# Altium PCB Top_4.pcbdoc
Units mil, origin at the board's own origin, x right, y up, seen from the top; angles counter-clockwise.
Board outline 3537.2 x 1973 mil, 4 copper layers (Top Layer, Inner1, Inner2, Bottom Layer), stack 97.3 mil thick; 147 components, 104 nets, 518 pads, 152 vias.
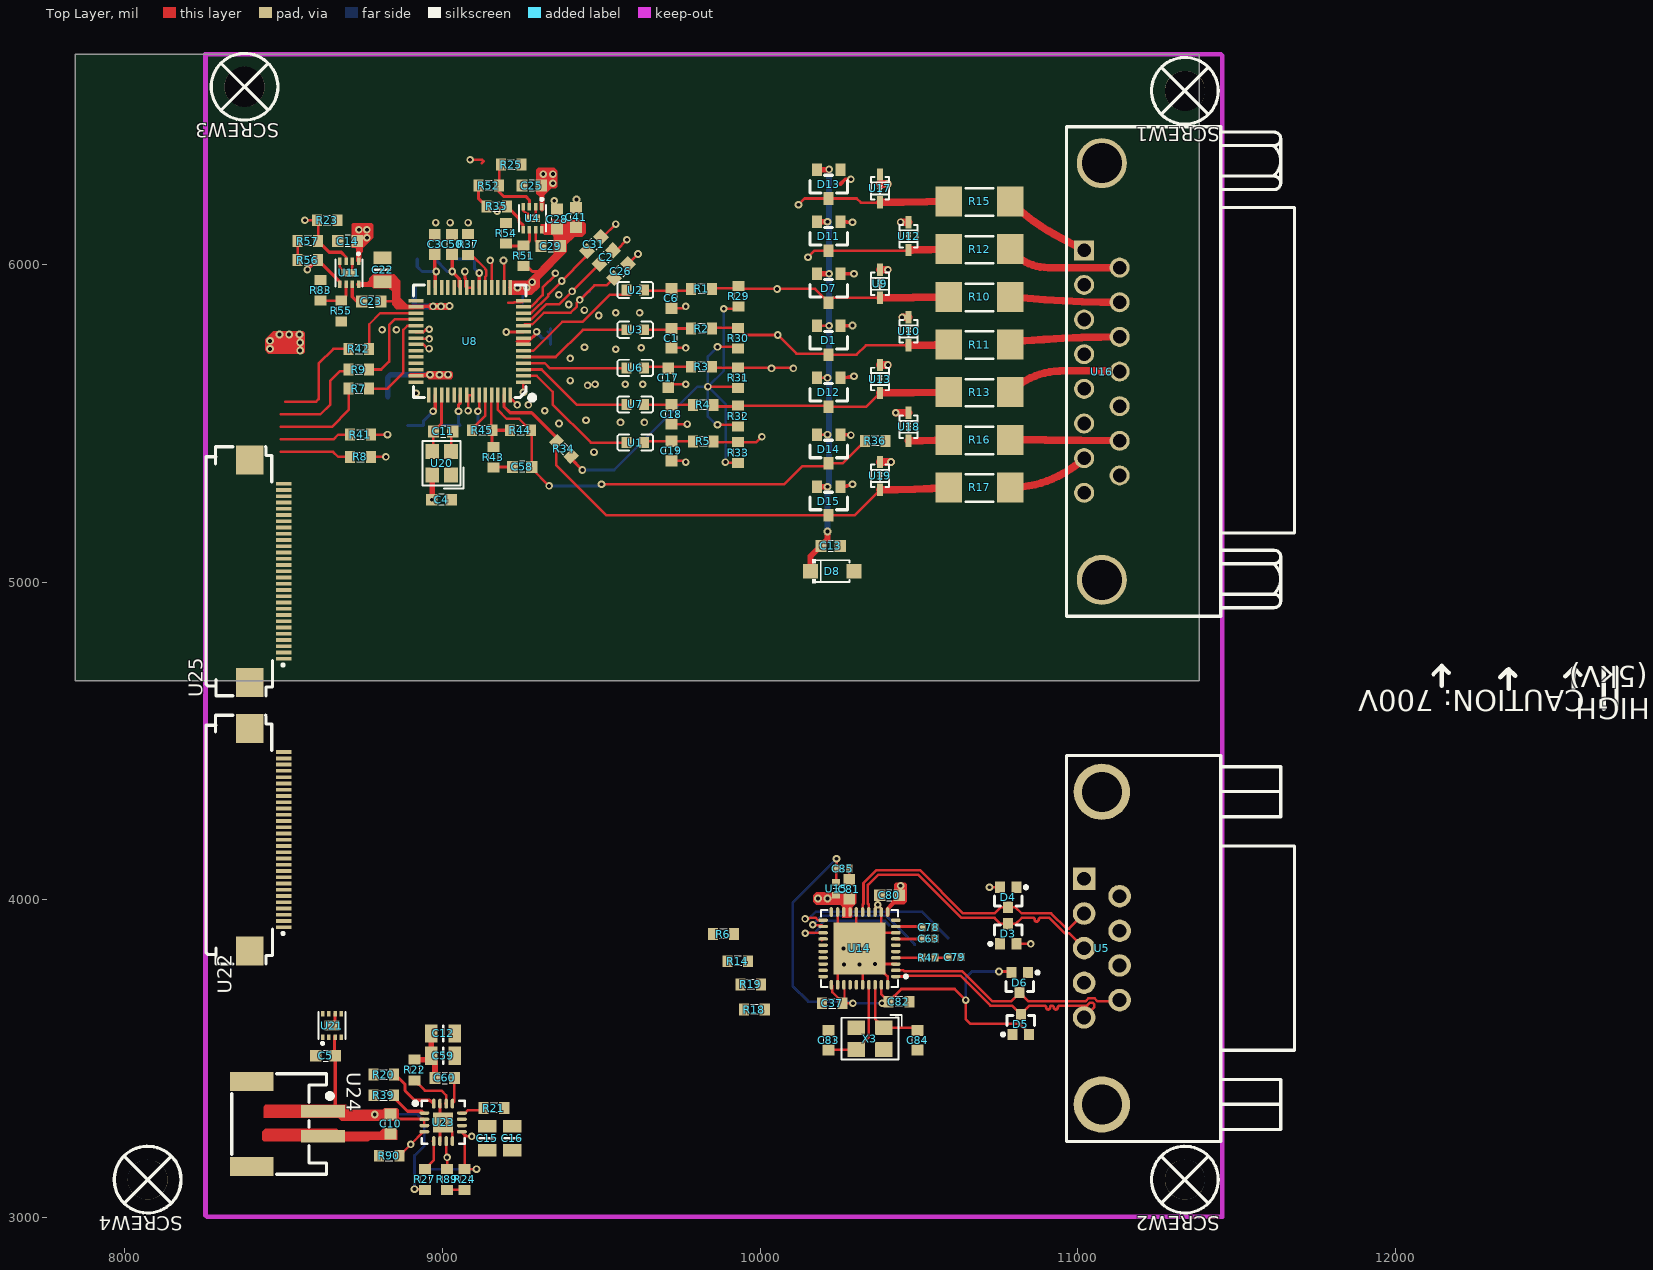
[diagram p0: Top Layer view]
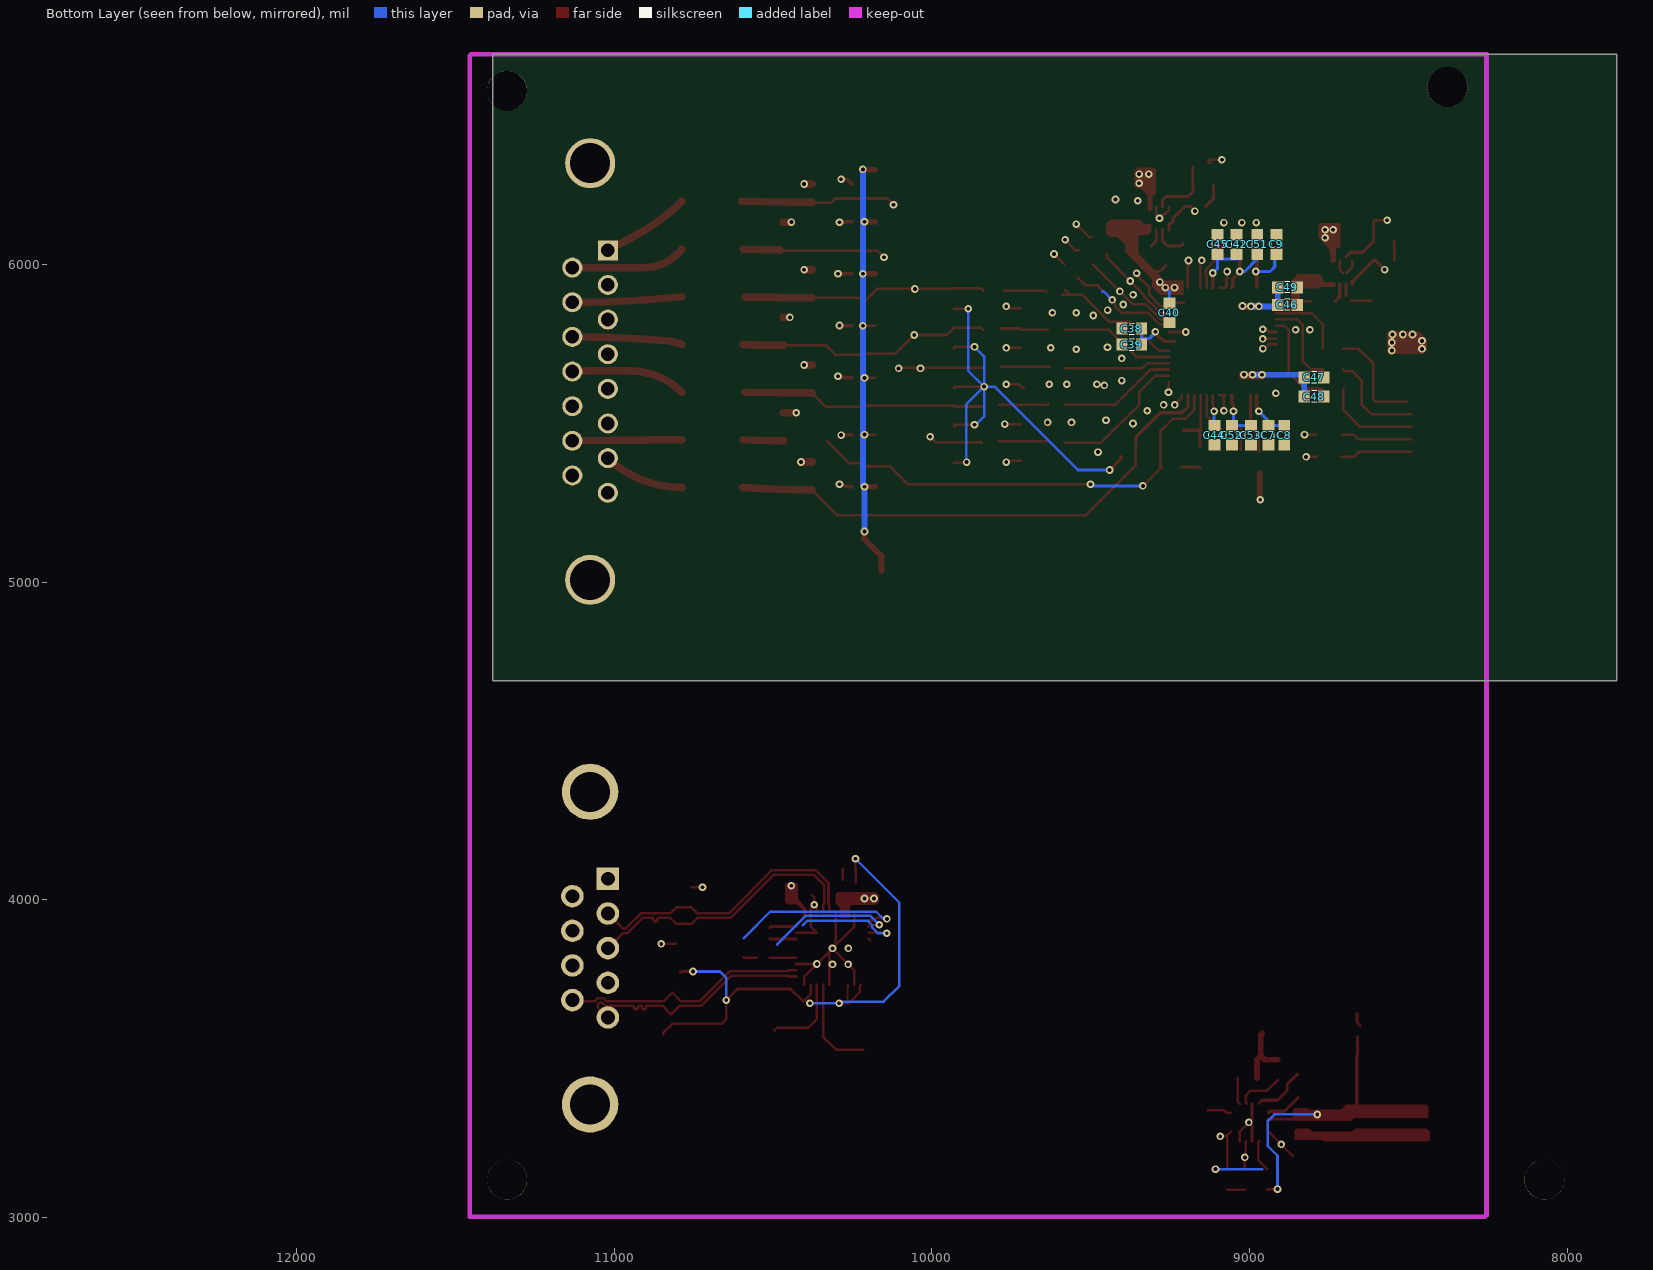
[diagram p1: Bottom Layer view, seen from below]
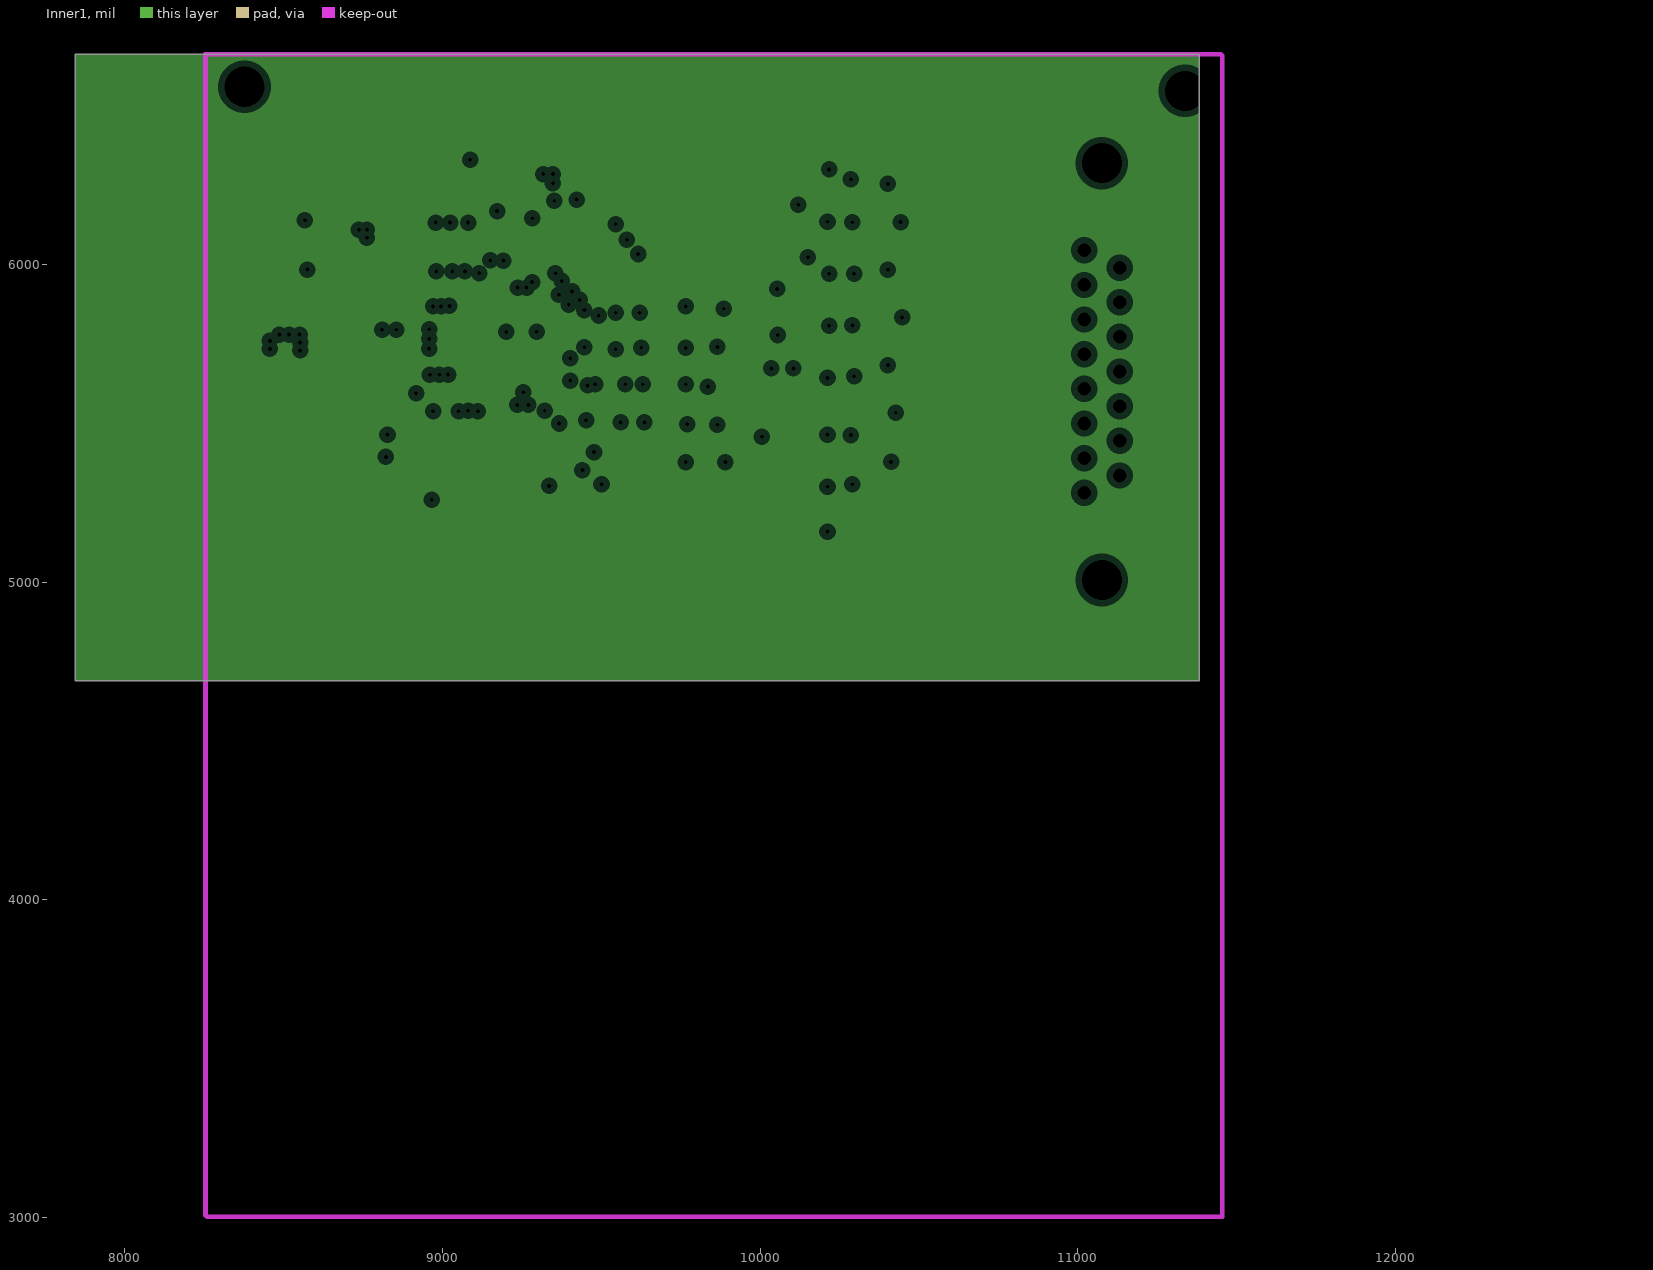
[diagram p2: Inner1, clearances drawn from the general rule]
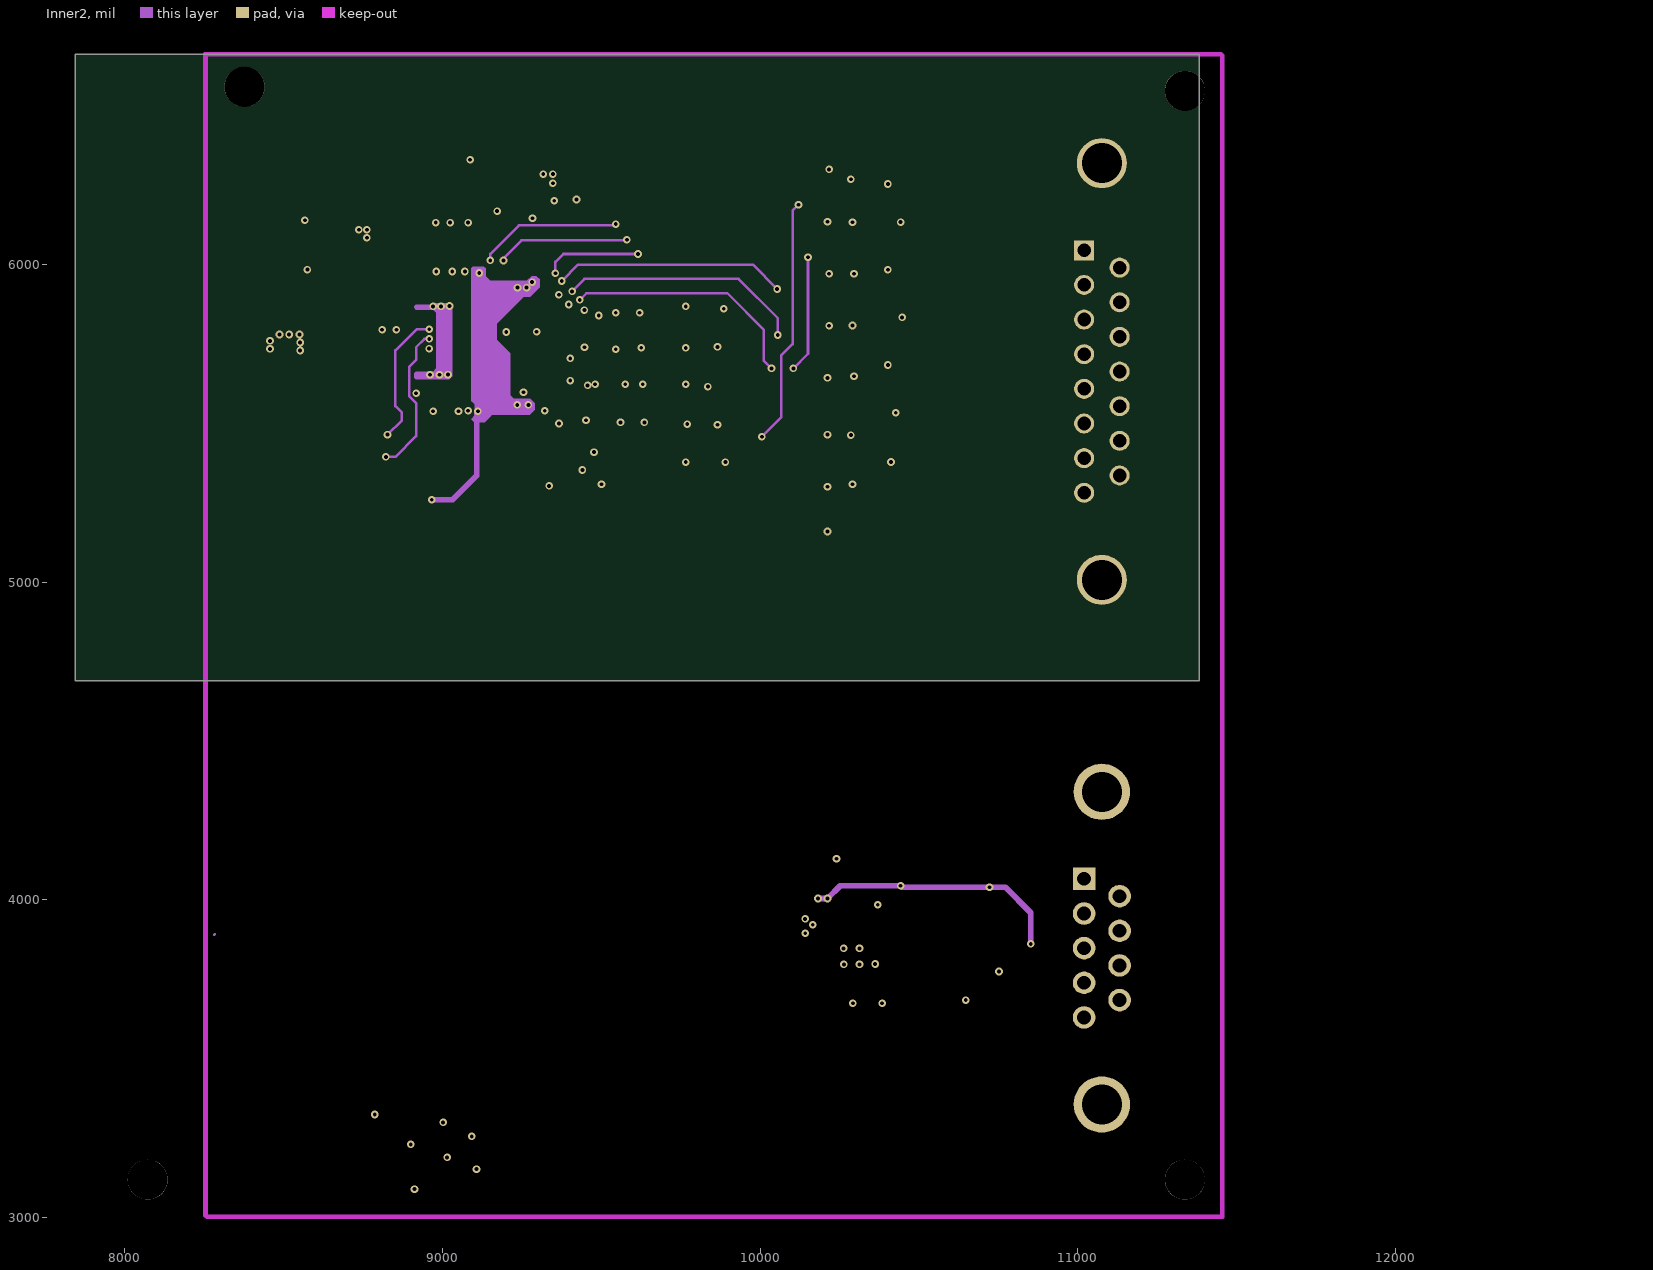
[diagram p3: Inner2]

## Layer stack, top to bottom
Top Solder Mask Layer: solder mask 0.4, Dk 3.3
Top Layer: signal copper 1.4
Inner1: plane copper (thickness not stored)
Inner2: signal copper (thickness not stored)
Dielectric2: surface 18.9, FR4, Dk 4.5
Dielectric3: surface 18.9, PP, Dk 4.5
Dielectric4: surface 18.9, PP, Dk 4.5
Dielectric5: surface 18.9, FR4, Dk 4.5
Dielectric6: surface 18.9, PP, Dk 4.5
Bottom Layer: signal copper 1.4
Bottom Solder Mask Layer: solder mask 0.4, Dk 3.3

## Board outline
7845,6662.7 11382.2,6662.7 11382.2,4689.7 7845,4689.7

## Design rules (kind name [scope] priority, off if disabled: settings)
BoardOutlineClearance copperThickness1oz [All] p0: genericclearance=10 ignorepadtopadclearanceinfootprint=FALSE except(0: Arc-SplitContinuation Track-SplitContinuation SMDPad-SplitContinuation THPad-SplitContinuation Via-SplitContinuation Fill-SplitContinuation Poly-SplitContinuation Region-SplitContinuation Text-SplitContinuation)
BoardOutlineClearance copperThickness2oz [All] p0: genericclearance=10 ignorepadtopadclearanceinfootprint=FALSE except(0: Arc-SplitContinuation Track-SplitContinuation SMDPad-SplitContinuation THPad-SplitContinuation Via-SplitContinuation Fill-SplitContinuation Poly-SplitContinuation Region-SplitContinuation Text-SplitContinuation)
BoardOutlineClearance copperThicknessInner0.5oz [All] p0: genericclearance=10 ignorepadtopadclearanceinfootprint=FALSE except(0: Arc-SplitContinuation Track-SplitContinuation SMDPad-SplitContinuation THPad-SplitContinuation Via-SplitContinuation Fill-SplitContinuation Poly-SplitContinuation Region-SplitContinuation Text-SplitContinuation)
BoardOutlineClearance otherClearance [All] p0: genericclearance=10 ignorepadtopadclearanceinfootprint=FALSE except(0: Arc-SplitContinuation Track-SplitContinuation SMDPad-SplitContinuation THPad-SplitContinuation Via-SplitContinuation Fill-SplitContinuation Poly-SplitContinuation Region-SplitContinuation Text-SplitContinuation)
Clearance copperThickness1oz [All] p1: gap=7 ignorepadtopadclearanceinfootprint=FALSE
Clearance copperThickness2oz [(InNet('AVDD') OR InNet('$28N49'))] p1: gap=7 ignorepadtopadclearanceinfootprint=FALSE
Clearance copperThicknessInner0.5oz [All] p1: gap=7 ignorepadtopadclearanceinfootprint=FALSE
Clearance otherClearance [All] p1: gap=7 ignorepadtopadclearanceinfootprint=FALSE
DiffPairsRouting differentialPair [All] p1: maxuncoupledlength=10 minlimit=5.9843 maxlimit=Infinity mostfreqgap=5.9843 toplayer_minwidth=5 toplayer_prefwidth=10 toplayer_maxwidth=100 bottomlayer_minwidth=5 bottomlayer_prefwidth=10 bottomlayer_maxwidth=100 midlayer1_minwidth=5 midlayer1_prefwidth=10 midlayer1_maxwidth=100
PasteMaskExpansion pasteMaskExpansion [All] p1: expansion=0
PlaneConnect innerPlane [All] p1: planeconnectstyle=Relief reliefexpansion=20 reliefentries=4 reliefconductorwidth=10 reliefairgap=10
PolygonConnect copperRegion [All] p1: connectstyle=Relief reliefentries=4 reliefconductorwidth=10 polygonreliefangle="90 Angle" airgapwidth=10
PolygonConnect copperRegion1 [All] p1: connectstyle=Direct reliefentries=4 reliefconductorwidth=10 polygonreliefangle="90 Angle" airgapwidth=10
RoutingVias viaSize [All] p1: viastyle="Through Hole" holewidth=12.0078 minholewidth=7.874 maxholewidth=248.0314 width=12.0078 minwidth=7.874 maxwidth=248.0314
SolderMaskExpansion solderMaskExpansion [IsVia] p1: useseparateexpansions=TRUE expansion=-1000 expansionbottom=-1000
SolderMaskExpansion solderMaskExpansion [All] p2: useseparateexpansions=TRUE expansion=2.0079 expansionbottom=2.0079
Width copperThickness1oz [All] p1: maxlimit=100 minlimit=4 preferedwidth=10
Width copperThickness2oz [All] p1: maxlimit=100 minlimit=8 preferedwidth=10
Width copperThickness0.5oz [All] p1: maxlimit=100 minlimit=4 preferedwidth=10

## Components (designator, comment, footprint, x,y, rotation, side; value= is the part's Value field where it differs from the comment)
C1 "100nF" C0603#1 9720.8,5768.3 r90 top
C2 "100nF" C0603#1 9515.8,6023.3 r45 top
C3 "100nF" C0603#1 8975.8,6063.3 r270 top
C4 "20pF" C0603#1 8997.2,5259.7 r180 top
C5 "100nF" C0603#1 8632.2,3509.7 r0 top
C6 "100nF" C0603#1 9720.8,5893.3 r90 top
C7 "100nF" C0603#1 8940.8,5463.3 r90 bottom
C8 "100nF" C0603#1 8890.8,5463.3 r90 bottom
C9 "100nF" C0603#1 8915.8,6063.3 r270 bottom
C10 "10uF" C0603#2 8837.2,3294.7 r90 top
C11 "20pF" C0603#1 9002.2,5474.7 r0 top
C12 "10uF" C0603#3 9002.2,3579.7 r0 top
C13 "10uF" C0603#1 10222.2,5114.7 r0 top
C14 "100nF" C0603#2 8701.5,6073.9 r180 top
C15 "10uF" C0603#3 9141,3249.5 r90 top
C16 "10uF" C0603#3 9219.8,3250.2 r90 top
C17 "100nF" C0603#1 9710.8,5643.3 r90 top
C18 "100nF" C0603#1 9720.8,5528.3 r90 top
C19 "100nF" C0603#1 9720.8,5413.3 r90 top
C22 "100nF" C0603#4 8811.5,5983.9 r270 top
C23 "100nF" C0603#5 8776.5,5883.9 r0 top
C25 "100nF" C0603#1 9280.8,6248.3 r180 top
C26 "100nF" C0603#6 9562.2,5979.7 r45 top
C28 "100nF" C0603#1 9360.8,6143.3 r270 top
C29 "100nF" C0603#1 9340.8,6058.3 r0 top
C31 "100nF" C0603#6 9477.2,6064.7 r45 top
C37 "100nF" C0603#7 10227.2,3674.7 r0 top
C38 "100nF" C0603#1 9370.8,5798.3 r180 bottom
C39 "100nF" C0603#1 9370.8,5748.3 r180 bottom
C40 "100nF" C0603#1 9252.3,5848 r90 bottom
C41 "100nF" C0603#1 9420.8,6148.3 r270 top
C42 "100nF" C0603#1 9040.8,6063.3 r270 bottom
C44 "100nF" C0603#1 9110.8,5463.3 r90 bottom
C45 "100nF" C0603#1 9100.8,6063.3 r270 bottom
C46 "100nF" C0603#1 8880.8,5873.3 r0 bottom
C47 "100nF" C0603#1 8797.2,5644.7 r0 bottom
C48 "100nF" C0603#1 8797.2,5584.7 r0 bottom
C49 "100nF" C0603#1 8880.8,5928.3 r0 bottom
C50 "100nF" C0603#1 9030.8,6063.3 r270 top
C51 "100nF" C0603#1 8975.8,6063.3 r270 bottom
C52 "100nF" C0603#1 9055.8,5463.3 r90 bottom
C53 "100nF" C0603#1 8995.8,5463.3 r90 bottom
C58 "100nF" C0603#1 9250.8,5363.3 r180 top
C59 "10uF" C0603#3 9002.2,3509.7 r0 top
C60 "100nF" C0603#1 9007.2,3439.7 r0 top
C63 "100nF" C0603#8 10530.8,3878.3 r180 top
C78 "100nF" C0603#8 10530.8,3913.3 r180 top
C79 "100nF" C0603#8 10612.2,3819.7 r180 top
C80 "100nF" C0603#1 10407.2,4014.7 r0 top
C81 "100nF" C0603#1 10280.8,4033.3 r270 top
C82 "100nF" C0603#7 10437.2,3679.7 r180 top
C83 "100nF" C0603#1 10215.8,3558.3 r270 top
C84 "100nF" C0603#1 10495.8,3558.3 r270 top
C85 "100nF" C0603#8 10260.8,4098.3 r180 top
D1 "BAV199LT1G" SOT-23_L2.9-W1.3-P1.90-LS2.4-BR#1 10215.8,5762 r90 top
D3 "BAV99W-7-F" SOT-323_L2.0-W1.3-P1.30-LS2.1-BR 10780.8,3893.3 r270 top
D4 "BAV99W-7-F" SOT-323_L2.0-W1.3-P1.30-LS2.1-BR 10780.8,4008.3 r90 top
D5 "BAV99W-7-F" SOT-323_L2.0-W1.3-P1.30-LS2.1-BR 10820.8,3608.3 r270 top
D6 "BAV99W-7-F" SOT-323_L2.0-W1.3-P1.30-LS2.1-BR 10817.3,3739.8 r90 top
D7 "BAV199LT1G" SOT-23_L2.9-W1.3-P1.90-LS2.4-BR#2 10215.8,5925.7 r90 top
D8 "SMF3.3A" SOD-123FL_L2.7-W1.8-LS3.7-RD 10227.2,5034.7 r0 top
D11 "BAV199LT1G" SOT-23_L2.9-W1.3-P1.90-LS2.4-BR#3 10215.8,6089.5 r90 top
D12 "BAV199LT1G" SOT-23_L2.9-W1.3-P1.90-LS2.4-BR#1 10215.8,5598.2 r90 top
D13 "BAV199LT1G" SOT-23_L2.9-W1.3-P1.90-LS2.4-BR#3 10215.8,6253.3 r90 top
D14 "BAV199LT1G" SOT-23_L2.9-W1.3-P1.90-LS2.4-BR#3 10215.8,5419.4 r90 top
D15 "BAV199LT1G" SOT-23_L2.9-W1.3-P1.90-LS2.4-BR#3 10215.8,5255.6 r90 top
R1 "10K" R0603#1 9815.8,5923.3 r180 top
R2 "10K" R0603#1 9815.8,5798.3 r180 top
R3 "10K" R0603#1 9815.8,5678.3 r180 top
R4 "10K" R0603#1 9820.8,5558.3 r180 top
R5 "10K" R0603#1 9820.8,5443.3 r180 top
R6 "10K" R0603#1 9884.7,3892.2 r180 top
R7 "10K" R0603#1 8737.2,5609.7 r0 top
R8 "10K" R0603#1 8742.2,5394.7 r0 top
R9 "10K" R0603#1 8737.2,5669.7 r0 top
R10 "5.1kΩ" R0207 10690.8,5898.3 r180 top
R11 "5.1kΩ" R0207 10690.8,5748.3 r180 top
R12 "5.1kΩ" R0207 10690.8,6048.3 r180 top
R13 "5.1kΩ" R0207 10690.8,5598.3 r180 top
R14 "10K" R0603#1 9929.7,3807.2 r180 top
R15 "5.1kΩ" R0207 10690.8,6199.1 r180 top
R16 "5.1kΩ" R0207 10690.8,5448.3 r180 top
R17 "5.1kΩ" R0207 10690.8,5298.3 r180 top
R18 "10K" R0603#1 9982.2,3654.7 r180 top
R19 "10K" R0603#2 9970.5,3734.4 r180 top
R20 "10K" R0603#2 8814.8,3450.2 r0 top
R21 "10K" R0603#1 9162.2,3344.7 r180 top
R22 "10K" R0603#3 8912.2,3464.7 r270 top
R23 "10K" R0603#1 8637.2,6139.7 r0 top
R24 "10K" R0603#1 9069.8,3120.2 r270 top
R25 "10K" R0603#1 9217.2,6314.7 r0 top
R27 "10K" R0603#1 8944.8,3120.2 r90 top
R29 "10K" R0603#3 9932.2,5899.7 r270 top
R30 "10K" R0603#1 9930.8,5768.3 r90 top
R31 "10K" R0603#1 9930.8,5643.3 r270 top
R32 "10K" R0603#1 9930.8,5523.3 r90 top
R33 "10K" R0603#1 9930.8,5408.3 r270 top
R34 "10K" R0603#4 9382.2,5419.7 r315 top
R35 "10K" R0603#1 9170.8,6183.3 r0 top
R36 "10K" R0603#1 10362.2,5444.7 r180 top
R37 "10K" R0603#1 9080.8,6063.3 r90 top
R39 "MF52" RES-TH_L2.5-W2.5-P1.70-D0.3 8814.8,3385.2 r0 top
R41 "10K" R0603#1 8742.2,5464.7 r0 top
R42 "10K" R0603#1 8737.2,5734.7 r0 top
R43 "10K" R0603#1 9160.8,5393.3 r90 top
R44 "10K" R0603#1 9245.8,5478.3 r180 top
R45 "10K" R0603#1 9125.8,5478.3 r180 top
R47 "10K" R0603#5 10530.8,3818.3 r180 top
R51 "10K" R0603#1 9255.8,6028.3 r270 top
R52 "10K" R0603#1 9145.8,6248.3 r180 top
R54 "10K" R0603#1 9200.8,6098.3 r270 top
R55 "10K" R0603#3 8681.5,5853.9 r270 top
R56 "10K" R0603#3 8576.5,6013.9 r0 top
R57 "10K" R0603#2 8576.5,6073.9 r180 top
R83 "10K" R0603#3 8616.5,5918.9 r270 top
R89 "10K" R0603#1 9014.8,3120.2 r270 top
R90 "10K" R0603#1 8832.2,3194.7 r0 top
SCREW1 "" M3螺丝 11337.2,6546.9 r180 top
SCREW2 "" M3螺丝 11337.2,3119.7 r180 top
SCREW3 "" M3螺丝 8377.2,6559.7 r180 top
SCREW4 "" M3螺丝 8072.2,3119.7 r180 top
U1 "YI160808U601-2R0T" L0603#1 9607.2,5439.7 r180 top
U2 "YI160808U601-2R0T" L0603#1 9607.2,5919.7 r180 top
U3 "YI160808U601-2R0T" L0603#1 9607.2,5794.7 r180 top
U4 "TPL9053AD-DF4R" TDFN-8_L2.0-W2.0-P0.50-BL-EP1.2-1#1 9283.5,6145.6 r270 top
U5 "D-SUB-DR-9PCM-CB" DB9-TH_D-SUB-DR-9PCM-CB 11075.8,3848.3 r90 top
U6 "YI160808U601-2R0T" L0603#1 9607.2,5674.7 r180 top
U7 "YI160808U601-2R0T" L0603#1 9607.2,5559.7 r180 top
U8 "" ? 9085.8,5758.3 r90 top
U9 "SP4024-01FTG-C" SOD-323_L1.8-W1.3-LS2.5-BI 10377.2,5939.7 r270 top
U10 "SP4024-01FTG-C" SOD-323_L1.8-W1.3-LS2.5-BI 10467.2,5789.7 r270 top
U11 "TPL9053AD-DF4R" TDFN-8_L2.0-W2.0-P0.50-BL-EP1.2-1#2 8706.5,5973.9 r270 top
U12 "SP4024-01FTG-C" SOD-323_L1.8-W1.3-LS2.5-BI 10467.2,6089.7 r270 top
U13 "SP4024-01FTG-C" SOD-323_L1.8-W1.3-LS2.5-BI 10377.2,5639.7 r270 top
U14 "AFE4400RHAR" VQFN-40_L6.0-W6.0-P0.50-TL-EP4.2 10312.9,3847.5 r180 top
U15 "BLM18PG121SN1D" L0603#2 10239.7,4034.9 r270 top
U16 "D-SUB-DR-15PCM-CB" DSUB-TH_XUNPU_D-SUB-DR-15PCM-CB 11075.8,5663.3 r90 top
U17 "SP4024-01FTG-C" SOD-323_L1.8-W1.3-LS2.5-BI 10377.2,6239.7 r270 top
U18 "SP4024-01FTG-C" SOD-323_L1.8-W1.3-LS2.5-BI 10467.2,5489.7 r270 top
U19 "SP4024-01FTG-C" SOD-323_L1.8-W1.3-LS2.5-BI 10377.2,5334.7 r270 top
U20 "8.192MHz" OSC-SMD_4P-L2.5-W2.0-BL 8997.2,5374.7 r90 top
U21 "MAX17048G+T10" TDFN-8_L2.0-W2.0-P0.50-BL-EP1.2 8652.2,3604.7 r0 top
U22 "AFD01-S29FCA-00" FPC-SMD_29P-P0.50_JS_AFD01-S29FCA-00 8447.2,4189.7 r90 top
U23 "BQ24072RGTR" QFN-16_L3.0-W3.0-P0.50-TL-EP 9002.2,3299.7 r0 top
U24 "ZX-PH2.0-WT2P" CONN-SMD_ZX-PH2.0-WT2P 8512.2,3294.7 r270 top
U25 "AFD01-S29FCA-00" FPC-SMD_29P-P0.50_JS_AFD01-S29FCA-00 8447.2,5034.7 r90 top
X3 "8MHz" CRYSTAL-SMD_4P-L3.2-W2.5-BL-1 10345.8,3563.3 r180 top

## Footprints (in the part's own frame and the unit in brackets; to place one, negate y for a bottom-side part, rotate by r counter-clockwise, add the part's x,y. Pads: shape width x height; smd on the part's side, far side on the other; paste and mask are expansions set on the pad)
C0603#1 [mil]
  rect 35.4x37.4 smd: 1(-30.5,0) 2(30.5,0)
  silkscreen extent -8,-18 8,18
C0603#2 [mil]
  rect 35.4x37.4 smd: 1(-30.5,0) 2(30.6,0)
  silkscreen extent -8,-18 8,18
C0603#3 [mil]
  rect 39.4x57.1 smd: 1(-37.4,0) 2(37.4,0)
  silkscreen extent 0,-25 0,25
C0603#4 [mil]
  rect 39.4x57.1 smd: 1(-37.4,0) 2(37.3,0)
  silkscreen extent 0,-25 0,25
C0603#5 [mil]
  rect 35.4x37.4 smd: 1(-30.6,0) 2(30.5,0)
  silkscreen extent -8,-18 8,18
C0603#6 [mil]
  rect 35.4x37.4 smd: 1(-30.48,0.07) 2(30.55,0)
  silkscreen extent -8,-18 8,18
C0603#7 [mil]
  rect 31.5x37.4 smd: 1(-32.5,0) 2(32.5,0)
  silkscreen extent -12,-15 12,15
C0603#8 [mil]
  rect 21.3x25.2 smd: 1(-20.1,0) 2(20.1,0)
  silkscreen extent 0,-10 0,10
CONN-SMD_ZX-PH2.0-WT2P [mil]
  rect 39.4x137.8 smd: 1(-39.4,112.2) 2(39.3,112.2)
  rect 59.1x137.8 smd: 3(-133.9,-112.2) 4(133.8,-112.2)
  silkscreen extent -158,-175 158,141
CRYSTAL-SMD_4P-L3.2-W2.5-BL-1 [mil]
  rect 55.1x47.2 smd: 1(-43.3,-34.4) 2(43.3,-34.4) 3(43.3,34.5) 4(-43.3,34.5)
  silkscreen extent -100,-75 90,65
DB9-TH_D-SUB-DR-9PCM-CB [mil]
  rect 70.9x70.9 hole 43.3: 1(218.1,55.9)
  round 70.9 hole 43.3: 2(109,55.9) 3(0,55.9) 4(-109.1,55.9) 5(-218.1,55.9) 6(163.6,-55.9) 7(54.5,-55.9) 8(-54.5,-55.9) 9(-163.6,-55.9)
  round 177.2 hole 126: 10(-492.1,0) 11(492.1,0)
  silkscreen extent -609,-606 606,111
DSUB-TH_XUNPU_D-SUB-DR-15PCM-CB [mil]
  rect 63x63 hole 42.9 paste+0 mask+2: 1(381.7,55.9)
  round 63 hole 42.9 paste+0 mask+2: 2(272.6,55.9) 3(163.6,55.9) 4(54.5,55.9) 5(-54.5,55.9) 6(-163.6,55.9) 7(-272.6,55.9) 8(-381.7,55.9) 9(327.2,-55.9) 10(218.1,-55.9) 11(109.1,-55.9) 12(0,-55.9) 13(-109.1,-55.9) 14(-218.1,-55.9) 15(-327.2,-55.9)
  round 157.5 hole 126 paste+0 mask+2: 16(-655.9,0) 17(655.9,0)
  silkscreen extent -770,-606 770,111
FPC-SMD_29P-P0.50_JS_AFD01-S29FCA-00 [mil]
  rect 11.8x49.2 smd paste+0 mask+2: 1(-275.5,-53.6) 2(-255.9,-53.6) 3(-236.2,-53.6) 4(-216.5,-53.6) 5(-196.8,-53.6) 6(-177.1,-53.6) 7(-157.4,-53.6) 8(-137.8,-53.6) 9(-118.1,-53.6) 10(-98.4,-53.6) 11(-78.7,-53.6) 12(-59,-53.6) 13(-39.3,-53.6) 14(-19.7,-53.6) 15(0,-53.6) 16(19.7,-53.6) 17(39.4,-53.6) 18(59.1,-53.6) 19(78.8,-53.6) 20(98.5,-53.6) 21(118.1,-53.6) 22(137.8,-53.6) 23(157.5,-53.6) 24(177.2,-53.6) 25(196.9,-53.6) 26(216.6,-53.6) 27(236.3,-53.6) 28(255.9,-53.6) 29(275.6,-53.6)
  rect 90.6x86.6 smd paste+0 mask+2: 30(350.4,53.6) 31(-350.4,53.6)
  silkscreen extent -392,-55 392,191
L0603#1 [mil]
  rect 31.5x34 smd paste-3937 mask+2: 1(-27.6,0) 2(27.6,0)
  silkscreen extent -56,-26 56,26
L0603#2 [mil]
  rect 21.3x25.2 smd: 1(-20.1,0) 2(20.1,0)
  silkscreen extent 0,-10 0,10
M3螺丝 [mil]
  round 126 hole 126 paste+0 mask+4: 1(0,0)
  silkscreen extent -105,-105 105,105
OSC-SMD_4P-L2.5-W2.0-BL [mil]
  rect 47.2x43.3 smd: 1(-37.4,-29.5) 2(37.4,-29.5) 3(37.4,29.5) 4(-37.4,29.5)
  silkscreen extent -79,-69 70,60
QFN-16_L3.0-W3.0-P0.50-TL-EP [mil]
  oval 31.5x11 smd: 1(-59.1,29.6) 2(-59.1,9.9) 3(-59.1,-9.8) 4(-59.1,-29.5) 9(59.1,-29.5) 10(59.1,-9.8) 11(59.1,9.9) 12(59.1,29.6)
  oval 11x31.5 smd: 5(-29.5,-59) 6(-9.8,-59) 7(9.8,-59) 8(29.5,-59) 13(29.5,59.1) 14(9.8,59.1) 15(-9.8,59.1) 16(-29.5,59.1)
  rect 63x63 smd: 17(0,0)
  silkscreen extent -94,-68 68,68
R0207 [mil]
  rect 82.7x94.5 smd: 1(-96.5,0) 2(96.5,0)
  silkscreen extent -44,-41 44,45
R0603#1 [mil]
  rect 31.5x37.4 smd: 1(-32.5,0) 2(32.5,0)
  silkscreen extent -12,-15 12,15
R0603#2 [mil]
  rect 31.5x37.4 smd: 1(-32.4,0) 2(32.5,0)
  silkscreen extent -12,-15 12,15
R0603#3 [mil]
  rect 31.5x37.4 smd: 1(-32.5,0) 2(32.4,0)
  silkscreen extent -12,-15 12,15
R0603#4 [mil]
  rect 31.5x37.4 smd: 1(-32.53,0) 2(32.46,0.07)
  silkscreen extent -12,-15 12,15
R0603#5 [mil]
  rect 21.3x25.2 smd: 1(-20.1,0) 2(20.1,0)
  silkscreen extent 0,-10 0,10
RES-TH_L2.5-W2.5-P1.70-D0.3 [mil]
  rect 31.5x37.4 smd: 1(-32.4,0) 2(32.5,0)
  silkscreen extent -12,-15 12,15
SOD-123FL_L2.7-W1.8-LS3.7-RD [mil]
  rect 47.2x45.3 smd: 1(-68.3,0) 2(68.3,0)
  silkscreen extent -63,-38 54,38
SOD-323_L1.8-W1.3-LS2.5-BI [mil]
  rect 38.8x19.3 smd: 1(-44,0) 2(44,0)
  silkscreen extent -36,-29 35,29
SOT-23_L2.9-W1.3-P1.90-LS2.4-BR#1 [mil]
  rect 39.4x31.5 smd: 1(45.2,-37.4) 2(45.2,37.4) 3(-45.3,0)
  silkscreen extent -28,-59 28,59
SOT-23_L2.9-W1.3-P1.90-LS2.4-BR#2 [mil]
  rect 39.4x31.5 smd: 1(45.3,-37.4) 2(45.3,37.4) 3(-45.2,0)
  silkscreen extent -28,-59 28,59
SOT-23_L2.9-W1.3-P1.90-LS2.4-BR#3 [mil]
  rect 39.4x31.5 smd: 1(45.3,-37.4) 2(45.3,37.4) 3(-45.3,0)
  silkscreen extent -28,-59 28,59
SOT-323_L2.0-W1.3-P1.30-LS2.1-BR [mil]
  rect 35.4x31.5 smd: 1(31.5,-25.6) 2(31.5,25.6) 3(-31.5,0)
  silkscreen extent -28,-61 36,43
TDFN-8_L2.0-W2.0-P0.50-BL-EP1.2 [mil]
  rect 11x16.7 smd: 1(-29.5,-36.9) 2(-9.8,-36.9) 3(9.8,-36.9) 4(29.5,-36.9) 5(29.5,37) 6(9.8,37) 7(-9.8,37) 8(-29.5,37)
  rect 47.2x31.5 smd: 9(0,0)
  silkscreen extent -42,-60 42,42
TDFN-8_L2.0-W2.0-P0.50-BL-EP1.2-1#1 [mil]
  rect 23x11 smd: 1(-36.1,29.6) 2(-36.1,9.9) 3(-36.1,-9.8) 4(-36.1,-29.5) 5(36.2,-29.5) 6(36.2,-9.8) 7(36.2,9.9) 8(36.2,29.6)
  rect 23.6x47.2 smd: 9(0,0)
  silkscreen extent -64,-42 42,42
TDFN-8_L2.0-W2.0-P0.50-BL-EP1.2-1#2 [mil]
  rect 23x11 smd: 1(-36.2,29.5) 2(-36.2,9.8) 3(-36.2,-9.9) 4(-36.2,-29.6) 5(36.1,-29.6) 6(36.1,-9.9) 7(36.1,9.8) 8(36.1,29.5)
  rect 23.6x47.2 smd: 9(0,0)
  silkscreen extent -64,-42 42,42
VQFN-40_L6.0-W6.0-P0.50-TL-EP4.2 [mil]
  oval 30.5x11 smd paste-3937 mask+2: 1(-114.4,88.5) 2(-114.4,68.9) 3(-114.4,49.2) 4(-114.4,29.5) 5(-114.4,9.8) 6(-114.4,-9.9) 7(-114.4,-29.6) 8(-114.4,-49.2) 9(-114.4,-68.9) 10(-114.4,-88.6) 21(114.5,-88.6) 22(114.5,-68.9) 23(114.5,-49.2) 24(114.5,-29.6) 25(114.5,-9.9) 26(114.5,9.8) 27(114.5,29.5) 28(114.5,49.2) 29(114.5,68.9) 30(114.5,88.5)
  oval 11x30.5 smd paste-3937 mask+2: 11(-88.5,-114.5) 12(-68.9,-114.5) 13(-49.2,-114.5) 14(-29.5,-114.5) 15(-9.8,-114.5) 16(9.9,-114.5) 17(29.6,-114.5) 18(49.3,-114.5) 19(68.9,-114.5) 20(88.6,-114.5) 31(88.6,114.4) 32(68.9,114.4) 33(49.3,114.4) 34(29.6,114.4) 35(9.9,114.4) 36(-9.8,114.4) 37(-29.5,114.4) 38(-49.2,114.4) 39(-68.9,114.4) 40(-88.5,114.4)
  rect 163.4x163.4 smd paste-3937 mask+2: 41(0,0)
  silkscreen extent -151,-121 121,121
? [mil]
  rect 11x47.2 smd: 1(-128,-169.3) 2(-108.3,-169.3) 3(-88.6,-169.3) 4(-68.9,-169.3) 5(-49.2,-169.3) 6(-29.5,-169.3) 7(-9.8,-169.3) 8(9.8,-169.3) 9(29.5,-169.3) 10(49.2,-169.3) 11(68.9,-169.3) 12(88.6,-169.3) 13(108.3,-169.3) 14(128,-169.3) 29(128,169.3) 30(108.3,169.3) 31(88.6,169.3) 32(68.9,169.3) 33(49.2,169.3) 34(29.5,169.3) 35(9.8,169.3) 36(-9.8,169.3) 37(-29.5,169.3) 38(-49.2,169.3) 39(-68.9,169.3) 40(-88.6,169.3) 41(-108.3,169.3) 42(-128,169.3)
  rect 47.2x11 smd: 15(169.3,-128) 16(169.3,-108.3) 17(169.3,-88.6) 18(169.3,-68.9) 19(169.3,-49.2) 20(169.3,-29.5) 21(169.3,-9.8) 22(169.3,9.8) 23(169.3,29.5) 24(169.3,49.2) 25(169.3,68.9) 26(169.3,88.6) 27(169.3,108.3) 28(169.3,128) 43(-169.3,128) 44(-169.3,108.3) 45(-169.3,88.6) 46(-169.3,68.9) 47(-169.3,49.2) 48(-169.3,29.5) 49(-169.3,9.8) 50(-169.3,-9.8) 51(-169.3,-29.5) 52(-169.3,-49.2) 53(-169.3,-68.9) 54(-169.3,-88.6) 55(-169.3,-108.3) 56(-169.3,-128)
  silkscreen extent -185,-205 177,177

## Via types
v1: diameter 24, hole 12, Top Layer to Bottom Layer, 152 vias

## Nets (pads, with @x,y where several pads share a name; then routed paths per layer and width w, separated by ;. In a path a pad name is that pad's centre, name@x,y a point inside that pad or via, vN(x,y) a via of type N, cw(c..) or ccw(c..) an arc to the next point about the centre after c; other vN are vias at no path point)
1ADC_RDY: R18.2 U22.14
1SCLK: R6.2 U22.22
1SPISIMO: R19.2 U22.18
1SPISOMI: R14.2 U22.20
1SPISTE: U14.27 U22.16
3V3: C80.2 C81.2 D3.2 D4.2 U14.11 U14.17 U14.18 U15.2 U22.28 U22.29 | length 898.5
  Top Layer w8: v1(10722.2,4039.8) D4.2 ; D3.2 v1(10852.2,3861.8)
  Inner2 w18: v1(10182.2,4004.7) v1(10212.2,4004.7) 10252.2,4044.7 v1(10442.2,4044.7) 10447.2,4039.8 v1(10722.2,4039.8) 10772.2,4039.8 10852.2,3959.7 v1(10852.2,3861.8)
$7N6: C78.2 U14.9 | length 84.7
  Top Layer w8: U14.9 10507.6,3916.4 C78.2
$7N32: D3.3 U5.3 U14.14 | length 905.5
  Top Layer w8: U14.14 10342.4,3985.3 10339.5,3988.1 10339.5,4047.1 10372.2,4079.7 10497.4,4079.7 10633.4,3943.8 10738.1,3943.8 10757.1,3924.8 D3.3 10804.6,3924.8 10823.6,3943.8 10858.6,3943.8 cw(c10858.6,3937.8) 10864.6,3937.8 ccw(c10870.6,3937.8) 10876.6,3937.8 cw(c10882.6,3937.8) 10882.6,3943.8 10910.6,3943.8 10958.6,3895.8 10972.4,3895.8 U5.3
$7N47: C84.1 U14.38 X3.1 | length 256.9
  Top Layer w8: U14.38 10362.1,3624.8 X3.1 10486.9,3597.7 C84.1
$7N48: C83.2 U14.37 X3.3 | length 307.9
  Top Layer w8: C83.2 10216.9,3528.8 X3.3 10342.4,3568.7 U14.37
$7N54: D4.3 U5.2 U14.15 | length 915
  Top Layer w8: U14.15 10322.7,3985.3 10325.6,3988.1 10325.6,4052.9 10366.4,4093.7 10503.2,4093.7 10639.2,3957.8 10738.1,3957.8 10757.1,3976.8 D4.3 10804.6,3976.8 10823.6,3957.8 10916.4,3957.8 10964.4,3909.8 10972.4,3909.8 U5.2@11019.9,3957.4
$7N84: R6.1 U14.24 | length 5.9
  Top Layer w8: U14.24@10194.2,3872.9 U14.24
$7N86: R14.1 U14.25
$7N88: R18.1 U14.28
$7N90: R19.1 U14.26
$28N10: C26.2 U8.13 | length 512.8
  Top Layer w8: U8.13 9256.8,5868.3 9280.4,5868.3 9315.8,5903.7 9315.8,5927.3 9355.8,5967.3 v1(9355.8,5972.9) ; C26.2 v1(9615.8,6033.3)
  Inner2 w8: v1(9355.8,5972.9) 9355.8,6008.3 9380.8,6033.3 v1(9615.8,6033.3)
$28N13: C2.2 U8.16 | length 563.1
  Top Layer w8: v1(9192.2,6012.7) 9194.1,6010.9 U8.16 ; C2.2 9547.4,6044.9 v1(9580.8,6078.3)
  Inner2 w8: v1(9192.2,6012.7) 9192.2,6019.8 9248.8,6076.3 9578.8,6076.3 v1(9580.8,6078.3)
$28N14: C31.2 U8.18 | length 605.3
  Top Layer w8: v1(9150.8,6013.3) 9154.7,6009.4 U8.18 ; C31.2 9504.8,6086.3 v1(9545.8,6127.3)
  Inner2 w8: v1(9150.8,6013.3) 9150.8,6033.3 9241,6123.6 9542.1,6123.6 v1(9545.8,6127.3)
$28N19: R29.2 R30.1 R31.2 R32.1 R33.2 R34.2 | length 1685.3
  Top Layer w8: v1(9835.8,5615.8) 9925.8,5615.8 R31.2 ; v1(9865.8,5495.8) 9925.8,5495.8 R32.1 ; v1(9865.8,5740.8) 9925.8,5740.8 R30.1 ; v1(9885.8,5860.8) R29.2@9930.8,5860.8 ; v1(9890.8,5378.3) 9893.3,5375.8 R33.2
  Top Layer w10: R34.2@9403.8,5395.3 9403.8,5390.3 v1(9440.8,5353.3)
  Bottom Layer w8: v1(9440.8,5353.3) 9540.8,5353.3 9803.3,5615.8 v1(9835.8,5615.8) ; v1(9865.8,5495.8) 9869.4,5499.4 9857.5,5499.4 9835.8,5521.1 v1(9835.8,5615.8) ; v1(9865.8,5740.8) 9835.8,5710.8 v1(9835.8,5615.8) ; v1(9885.8,5860.8) 9885.8,5665.8 v1(9835.8,5615.8) ; v1(9890.8,5378.3) 9892.2,5379.7 9892.2,5559.4 v1(9835.8,5615.8)
$28N49: C38.2 C39.2 U8.7 U8.8 | length 221.1
  Top Layer w10: 9235.8,5758.3 9270.8,5758.3 9296.7,5784.2 v1(9296.7,5788.3)
  Bottom Layer w8: C38.2@9331.8,5788.3 9340.3,5779.9 9341.3,5778.9 ; 9341.3,5768.3 9340.3,5768.3 9311.8,5768.3 ; 9311.8,5768.3 9296.7,5783.5 v1(9296.7,5788.3) 9311.8,5773.2 9311.8,5768.3
  Bottom Layer w10: C39.2 9340.3,5768.3 9340.3,5779.9 C38.2
$28N62: R37.1 U8.19 | length 134
  Top Layer w8: R37.1 9091.1,6030.8 9135,5986.9 9135,5985.2 9137.8,5982.4 9137.8,5964.2 9135,5961.4 U8.19
$28N73: R41.2 U8.34 | length 508.6
  Top Layer w8: R41.2@8789.7,5464.7 v1(8827.2,5464.7) ; U8.34 8940.1,5787.8 8948.4,5796.2 v1(8958.4,5796.2)
  Inner2 w8: v1(8827.2,5464.7) 8872.2,5509.7 8872.2,5534.7 8852.2,5554.7 8852.2,5684.7 8852.3,5684.9 8852.3,5729.9 8918.6,5796.2 v1(8958.4,5796.2)
$28N74: R42.2 U8.31 | length 238.7
  Top Layer w8: R42.2 8769.7,5812.2 8804.3,5846.9 U8.31
$28N75: C58.2 R43.1 | length 60.5
  Top Layer w10: R43.1@9155.8,5360.8 9158.3,5363.3 C58.2@9215.3,5363.3
$28N223: C6.2 R1.2 U2.1 | length 135
  Top Layer w8: U2.1@9639.8,5914.7 9643.3,5918.3 R1.2@9773.3,5918.3
$28N224: U2.2 U8.6 | length 428.5
  Top Layer w8: U8.6 9286.2,5728.8 9377.2,5819.7 9441.1,5819.7 9526.1,5904.7 U2.2@9564.6,5904.7 ; U2.2 U2.2@9564.6,5904.7 ; U2.2@9589.6,5904.7 U2.2@9564.6,5904.7
$28N225: C1.2 R2.2 U3.1 | length 150.4
  Top Layer w8: U3.1 9716.7,5794.7 C1.2 9782.8,5798.8 R2.2
$28N226: U3.2 U8.5 | length 359.9
  Top Layer w8: U8.5 9356.5,5709.1 9442.2,5794.7 U3.2
$28N227: C17.2 R3.2 U6.1 | length 154.9
  Top Layer w8: U6.1@9628.4,5678.3 R3.2
$28N228: U6.2 U8.4 | length 331.7
  Top Layer w8: U8.4 9322.5,5689.4 9338.7,5673.3 9578.2,5673.3 U6.2
$28N229: C18.2 R4.2 U7.1 | length 157
  Top Layer w8: U7.1@9633.4,5563.3 9638.4,5558.3 R4.2
$28N230: U7.2 U8.3 | length 371.2
  Top Layer w8: U8.3 9312.2,5669.7 9423.7,5558.3 9578.2,5558.3 U7.2
$28N231: C19.2 R5.2 U1.1 | length 149.9
  Top Layer w8: U1.1@9638.4,5443.3 R5.2
$28N232: U1.2 U8.2 | length 435
  Top Layer w8: U8.2 9296.9,5650 9347.2,5599.7 9347.2,5559.7 9467.2,5439.7 U1.2
$28N273: C29.1 U4.7 | length 58.1
  Top Layer w8: U4.7 9293.4,6075.2 C29.1
$28N274: C23.1 U11.7 | length 59.9
  Top Layer w10: U11.7 8716.3,5898.6 C23.1@8730.9,5883.9
$28N301: R16.2 R36.1 U18.2 | length 127.2
  Top Layer w24: U18.2 ccw(c10467.2,8615.1) R16.2@10594.39,5448.25
$28N326: C31.1 D7.3 R1.1 R10.2 R29.1 U8.12 U9.2 | length 1786.8
  Top Layer w8: U8.12 9279.4,5846.9 9333.8,5901.3 9333.8,5906.3 v1(9375.8,5948.3) 9449.2,6021.7 C31.1@9449.2,6031.7 ; R1.1@9838.3,5918.3 9845.8,5925.8 9930.8,5925.8 9933.3,5923.3 v1(10053.6,5923.3) 10173,5923.3 D7.3 10231.1,5895.7 U9.2
  Top Layer w24: U9.2 ccw(c10377.2,15137.7) R10.2@10586.88,5898.08
  Inner2 w8: v1(9375.8,5948.3) 9427.3,5999.7 9977.1,5999.7 v1(10053.6,5923.3)
$28N328: C2.1 D1.3 R2.1 R11.2 R30.2 U8.11 U10.2 | length 1881.8
  Top Layer w8: U8.11 9278.7,5827.2 9326.2,5874.7 9367.3,5874.7 v1@9405.8,5913.3 ; v1(9408.2,5915.7) C2.1 ; R2.1@9838.3,5793.3 9845.8,5800.8 R30.2 9953.3,5778.3 v1(10055.8,5778.3) 10114.4,5719.7 10212.7,5719.7 D1.3 10304.1,5716.7 10333.2,5745.7 U10.2
  Top Layer w24: U10.2 ccw(c10467.2,8915.1) R11.2@10594.39,5748.25
  Inner2 w8: v1(9408.2,5915.7) 9447.3,5954.7 9932.2,5954.7 10055.8,5831.1 v1(10055.8,5778.3)
$28N330: C26.1 D11.3 R3.1 R12.2 R31.1 U8.10 U12.2 | length 2255
  Top Layer w8: U8.10 9259.3,5811.7 9282.9,5811.7 9319.5,5848.3 9403.4,5848.3 9422.2,5867.1 9422.2,5878.4 v1(9432.5,5888.7) 9478.6,5934.7 9517.2,5934.7 C26.1 ; R3.1@9838.3,5673.3 9840.8,5675.8 R31.1 10102.3,5675.8 v1(10104.8,5673.3) ; v1(10150.8,6023.3) 10171.8,6044.2 D11.3 10477.6,6044.2 10479.1,6045.8
  Top Layer w24: 10478.26,6045.72 ccw(c10467.2,9215.1) R12.2@10594.39,6048.25
  Inner2 w8: v1(9432.5,5888.7) 9453.6,5909.7 9897.2,5909.7 10012.2,5794.7 10012.2,5696.9 v1(10035.8,5673.3) ; v1(10104.8,5673.3) 10150.8,5719.3 v1(10150.8,6023.3)
  Bottom Layer w8: v1(9432.5,5888.7) 9458.6,5914.7 9463.6,5914.7
$28N332: D12.3 R4.1 R13.2 R32.2 U13.2 | length 763.6
  Top Layer w8: R4.1@9843.3,5553.3 9928.3,5553.3 R32.2 10212.9,5555.8 D12.3 10334.4,5552.9 U13.2
  Top Layer w24: U13.2 ccw(c10377.2,14837.7) R13.2@10586.88,5598.08
$28N346: D15.3 R17.2 R34.1 U8.55 U19.2 | length 1664.1
  Top Layer w8: R34.1@9357.8,5441.3 9357.8,5369.1 9516.6,5210.3 D15.3 10296.8,5210.3 U19.2
  Top Layer w10: U8.55 9193.7,5588.7 9193.7,5553.2 9213.7,5533.3 9280.8,5533.3 9357.8,5456.3 R34.1@9357.8,5441.3
  Top Layer w24: U19.2@10377.2,5290.8 ccw(c10377.2,8416.6) R17.2@10595.24,5298.41
$28N348: D13.3 R5.1 R15.2 R33.1 U17.2 | length 1440.8
  Top Layer w8: R5.1@9843.3,5438.3 9845.8,5440.8 R33.1 9988.3,5440.8 v1(10005.8,5458.3) ; v1(10120.8,6188.3) 10140.5,6208 D13.3 10303.9,6208 10317.2,6194.7 10376.2,6194.7 U17.2
  Top Layer w24: U17.2@10377.2,6195.8 ccw(c10377.2,13258.6) R15.2@10599.05,6199.29
  Inner2 w8: v1(10005.8,5458.3) 10067.2,5519.7 10067.2,5714.7 10102.2,5749.7 10102.2,6169.7 v1(10120.8,6188.3)
$28N378: R9.2 U8.32 | length 279.4
  Top Layer w8: R9.2 8807.2,5669.7 8832.2,5694.7 8832.2,5809.7 8849.7,5827.2 U8.32
$28N380: R7.2 U8.33 | length 307.8
  Top Layer w8: R7.2 8827.2,5609.7 8877.2,5659.7 8877.2,5792.6 8877.3,5792.7 8877.3,5794.9 8890,5807.5 U8.33
$28N382: R8.2 U8.35 | length 547.5
  Top Layer w8: R8.2@8789.7,5394.7 v1(8822.2,5394.7) ; U8.35 8918.5,5766.2 v1(8958.4,5766.2)
  Inner2 w8: v1(8822.2,5394.7) 8852.2,5394.7 8917.2,5459.7 8917.2,5563.6 8895.2,5585.6 8895.2,5677.8 8917.2,5699.7 8917.2,5739.7 8943.6,5766.2 v1(8958.4,5766.2)
$30N9: R39.2 U23.1 | length 112.8
  Top Layer w10: R39.2@8847.7,3377.3 8890.2,3334.7 8935.8,3334.7 U23.1@8940.8,3329.7
$30N11: R27.2 U23.5 | length 100.6
  Top Layer w8: R27.2 8972.2,3180 8972.2,3239.2 U23.5@8970.3,3241.1
$30N18: R22.2 U23.14 | length 146.3
  Top Layer w8: R22.2 8944.7,3399.7 8997.2,3399.7 9012.2,3384.7 9012.2,3361.8 U23.14@9009.7,3359.2
$30N19: R21.2 U23.12 | length 76.5
  Top Layer w8: U23.12@9058.9,3329.7 9072.2,3329.7 9079.7,3337.3 R21.2@9132.2,3337.3
$30N20: R20.2 U23.16 | length 172.4
  Top Layer w10: R20.2 8851.8,3450.2 8882.2,3419.7 8882.2,3399.7 8912.2,3369.7 8959.8,3369.7 U23.16@8970.3,3359.2
+VPS: C13.1 C14.1 C15.2 C16.2 C25.1 D1.2 D7.2 D8.1 D11.2 D12.2 D13.2 D14.2 D15.2 R24.2 R35.1 R52.2 R56.1 R57.2 R89.2 U4.1 U11.1 U22.8 U22.9 U23.10 U23.11 U25.28 U25.29 | length 1733.3
  Top Layer w8: R56.1 R57.2 ; R89.2 R24.2 ; D14.2 v1(10212.2,5464.7) ; D12.2 v1(10212.2,5643.4) ; D1.2 v1(10217.2,5807.2)
  Top Layer w10: R52.2 9113.3,6208.3 R35.1
  Top Layer w18: D8.1 10158.9,5081.9 C13.1 10212.2,5135.3 v1(10212.2,5159.7) ; D15.2 v1(10212.2,5300.9) ; D7.2 v1(10217.2,5971) ; D11.2 v1(10212.2,6134.8) ; D13.2 10216,6298.6 v1(10217.2,6299.7)
  Inner2 w8: 8282.2,3891 8283.5,3892.3
  Bottom Layer w18: v1(10212.2,5159.7) v1(10212.2,5300.9) 10217.2,5305.9 v1(10217.2,5807.2) v1(10217.2,5971) v1(10217.2,6299.7)
  other v1: 8552.2,5729.7 8457.2,5734.7 8552.2,5754.7 8457.2,5759.7 8487.2,5779.7 8517.4,5779.7 8550.3,5779.7 8762.2,6084.7 8737.2,6109.7 8762.2,6109.7 9347.8,6255.7 9317.2,6284.7 9347.8,6284.7
ACS: R8.1 U25.12 | length 225.6
  Top Layer w8: 8490.8,5410.7 8656.3,5410.7 8672.2,5394.7 R8.1
ADCVDD: C50.2 C51.2 C52.2 C53.2 U8.23 U8.48 | length 326.7
  Top Layer w10: C50.2@9030.8,6017.8 9030.8,5978 9053.1,5955.8 9053.1,5930.8 U8.23 ; v1(9050.8,5538.3) 9050.8,5558.5 9056.3,5564 U8.48
  Bottom Layer w10: C51.2@8975.8,6017.8 9015.3,5978.3 v1(9030.8,5978.3) ; C53.2@9000.8,5493.8 C52.2 9050.8,5498.8 v1(9050.8,5538.3)
ADRDY: R41.1 U25.14 | length 225
  Top Layer w8: 8490.8,5450 8657.5,5450 8672.2,5464.7 R41.1
AGND: C1.1 C3.1 C4.1 C5.1 C6.1 C7.1 C8.1 C9.1 C10.1 C11.2 C12.1 C13.2 C14.2 C15.1 C16.1 C17.1 C18.1 C19.1 C22.1 C25.2 C28.1 C37.1 C38.1 C39.1 C40.1 C41.1 C42.1 C44.1 C45.1 C46.1 C47.1 C48.1 C49.1 C50.1 C51.1 C52.1 C53.1 C59.1 C60.1 C63.1 C78.1 C79.1 C80.1 C81.1 C82.1 C83.1 C84.2 C85.1 D1.1 D3.1 D4.1 D5.1 D6.1 D7.1 D8.2 D11.1 D12.1 D13.1 D14.1 D15.1 R20.1 R21.1 R22.1 R23.2 R25.2 R39.1 R54.1 R83.1 R90.1 SCREW1.1 SCREW2.1 SCREW3.1 SCREW4.1 U4.2 U4.4 U4.9 U5.7 U5.10 U5.11 U8.1 U8.9 U8.14 U8.21 U8.22 U8.28 U8.29 U8.36 U8.42 U8.43 U8.49 U8.50 U9.1 U10.1 U11.2 U11.4 U11.9 U12.1 U13.1 U14.3 U14.8 U14.12 U14.13 U14.16 U14.19 U14.32 U14.36 U14.40 U14.41 U16.6 U16.16 U16.17 U17.1 U18.1 U19.1 U20.2 U21.1 U21.6 U21.9 U22.1 U22.7 U22.10 U22.13 U22.15 U22.17 U22.19 U22.21 U22.23 U22.27 U23.6 U23.8 U23.15 U23.17 U24.2 U24.3 U24.4 U25.11 U25.13 U25.15 U25.17 U25.19 U25.21 U25.26 U25.27 X3.2 X3.4 | length 2684.8
  Top Layer w8: U21.9 8662,3614.6 U21.6 ; U11.4 8676.9,5992.2 U11.9@8695.2,5973.9 ; U11.9 8716.3,5983.8 U11.2 ; U8.36 8940.1,5748.5 8953.1,5735.5 v1(8958.1,5735.5) ; U23.6 8992.4,3289.9 v1(9002.2,3299.7) ; U23.15 8992.4,3309.6 v1(9002.2,3299.7) ; U20.2@9026.7,5417.1 9027.7,5418.1 C11.2@9027.7,5484.7 ; U23.8 9031.7,3270.2 v1(9002.2,3299.7) ; U8.22 U8.21 ; v1(9080.8,5539.9) 9080.8,5584.2 U8.49 U8.50 ; v1(9200.8,5787.8) U8.9 ; 9207.2,5879.7 9225,5879.7 9227.3,5882.1 9250.9,5882.1 U8.14 ; U4.4 9254,6170.2 9264.1,6160.2 9268.9,6160.2 v1(9283.5,6145.6) 9293.4,6155.4 U4.2 ; v1(9255.1,5598.3) U8.1 ; C17.1 9715.8,5612.8 9726.3,5623.3 v1(9765.8,5623.3) ; C19.1 9761.3,5382.8 v1(9765.8,5378.3) ; C18.1 v1(9770.8,5497.8) ; C1.1 v1(9765.8,5737.8) ; C6.1 9760.3,5862.8 v1(9765.8,5868.3) ; U14.32 10244,3778.6 v1(10312.9,3847.5) U14.41@10322.7,3837.7 ; U14.19 10244,3916.4 10303,3857.4 U14.16 ; C81.1 10280.9,4063.9 C85.1 ; U14.36 U14.41@10322.7,3837.7 ; U14.13 10362.2,3962.1 10362.2,3974.1 10370.2,3982.1 v1(10370.2,3984.7) ; C80.1 10370.2,4008.3 v1(10370.2,3984.7) ; U14.40 10401.4,3759 v1(10362.1,3798.3) ; U14.3 v1(10362.1,3798.3) ; U14.8 10362.1,3896.7 10381.8,3916.4 U14.12 10381.8,3973.2 v1(10370.2,3984.7) ; U14.41@10322.7,3837.7 v1(10362.1,3798.3)
  Top Layer w10: v1(9070.8,5978.3) 9070.8,5957.7 9072.8,5955.8 9072.8,5930.8 U8.22
  Top Layer w12: D15.1 ccw(c10253.2,5400) v1(10290.8,5308.3) ; D14.1@10253.2,5464.6 cw(c10253.2,5076.8) v1@10285.65,5463.24 ; D12.1@10253.2,5643.5 ccw(c10253.2,5833.1) v1@10295.85,5648.36 ; D1.1@10253.2,5807.3 ccw(c10253.2,6470.6) v1@10290.23,5808.33 ; D7.1 v1(10295.8,5971) ; D11.1 cw(c10253.2,5661.1) v1@10291.19,6133.27 ; 10253.2,6253.6 10268.2,6268.6 v1(10285.8,6268.6)
  Top Layer w18: R22.1 8952.3,3497.2 C59.1 ; C12.1@8959.8,3579.7 8964.8,3574.7 C59.1 ; C60.1 8976.7,3497.9 C59.1
  Top Layer w24: U19.1 v1(10412.2,5378.7) ; U13.1 v1(10402.2,5683.7) ; U9.1 v1(10402.2,5983.7) ; 10377.2,6253.7 v1(10402.2,6253.7) ; v1(10427.2,5533.7) U18.1 ; v1(10442.2,6133.7) U12.1 ; v1(10447.2,5833.7) U10.1
  other v1: 10263.8,3797 10312.9,3797 10262.9,3847.5 9477.2,5409.7 10285.8,5463.3 9367.2,5499.7 9560.8,5503.3 9635.8,5503.3 9452.2,5509.7 9322.2,5539.7 8917.2,5594.7 9457.2,5619.7 9480.8,5623.3 9575.8,5623.3 9630.8,5623.3 9402.2,5634.7 10295.8,5648.3 9402.2,5704.8 9545.8,5733.3 9625.8,5738.3 9447.2,5739.7 8810.2,5794.7 8855.3,5794.7 10290.8,5808.3 9492.2,5839.7 9545.8,5848.3 9620.8,5848.3 9447,5856.7 9397.8,5874.2 9366.7,5905.3 8978.8,6132.2 9024.2,6132.2 9080.8,6132.2 10290.8,6133.3 9351.8,6200.9 9422.2,6204.7
ASCLK: R9.1 U25.18 | length 316.2
  Top Layer w8: 8490.8,5528.8 8616.2,5528.8 8647.2,5559.7 8647.2,5634.7 8677.2,5664.7 8699.7,5664.7 R9.1
ASCO: R42.1 U25.20 | length 333.4
  Top Layer w8: 8505.8,5568.2 8602.6,5568.2 8610.6,5576.2 8610.6,5688.2 8657.2,5734.7 R42.1
ASDI: R7.1 U25.16 | length 303.2
  Top Layer w8: 8490.8,5489.4 8651.9,5489.4 8704.7,5542.3 R7.1
AVDD: C4.2 C28.2 C29.2 C40.2 C41.2 C42.2 C44.2 C45.2 R51.2 U4.8 U8.15 U8.20 U8.51 U8.56 U20.4 | length 1096.4
  Top Layer w8: v1(9111.6,5538.3) 9115.3,5542 U8.51 ; U8.56 9213.8,5580.3 v1(9235.8,5558.3)
  Top Layer w10: R51.2@9263.3,5998.3 9283.4,5978.3 9300.8,5978.3
  Top Layer w11: U8.20 9115.5,5927.8 9115.5,5957 9115.8,5957.3 v1(9115.8,5973.3)
  Top Layer w16: U8.15@9214.1,5927.6 v1(9236.6,5927.6)
  Top Layer w18: v1(8966.7,5259.7) 8967.7,5260.7 U20.4@8967.7,5342.3
  Inner2 w16: v1(9111.6,5538.3) 9131.6,5558.3 v1(9235.8,5558.3) v1(9270.8,5558.3) ; v1(9236.6,5927.6) v1(9265.1,5927.6) v1(9282.3,5944.8)
  Inner2 w18: v1(8966.7,5259.7) 9032.2,5259.7 9107.8,5335.3 9107.8,5530.3 9111.6,5534.2 v1(9111.6,5538.3)
  Bottom Layer w8: C40.2 9252.3,5914.8 v1(9265.1,5927.6)
  Bottom Layer w10: C42.2@9040.8,6017.8 9100.8,6017.8 9100.8,5988.3 v1(9115.8,5973.3) ; C44.2 9111.6,5494.6 v1(9111.6,5538.3)
BAT: C5.2 C10.2 R27.1 U21.3 U23.2 U23.3 U24.1 | length 895.9
  Top Layer w8: v1(8912.2,3089.7) 8942.8,3089.7 R27.1 ; U23.3 U23.2
  Top Layer w10: 8546.5,3334.1 8662.7,3334.1 C5.2 8660.2,3512.2 U21.3@8660.2,3569.3 ; C10.2@8845.4,3320.2 8855.5,3310 U23.2@8940.8,3310
  Bottom Layer w8: v1(8787.2,3324.7) 8922.2,3324.7 8942.2,3304.7 8942.2,3224.7 8912.2,3194.7 v1(8912.2,3089.7)
BAT_CE: R90.2 U22.6 U23.4 | length 107.6
  Top Layer w8: R90.2 v1(8900.4,3230.4) 8940.6,3270.7 U23.4@8940.8,3270.7
BAT_CHG1: R24.1 U22.4 U23.9 | length 331
  Top Layer w8: U23.9@9058.9,3270.7 9069.8,3259.7 ; v1(9092.2,3255.7) 9076.3,3255.7 9072.2,3259.7 9069.8,3259.7 ; v1(9107.2,3152.7) R24.1 9069.8,3259.7
  Bottom Layer w8: 8960.1,3152.7 v1(9107.2,3152.7)
BAT_PGOOD: R89.1 U22.5 U23.7 | length 92.8
  Top Layer w8: U23.7 9012,3192.5 v1(9014.8,3189.7) R89.1
  Bottom Layer w8: v1@9012.2,3187.1 v1(9014.8,3189.7)
BATT_SCL: U21.7 U22.3
BATT_SDA: U21.8 U22.2
CAL_DAC_IO: U8.17
CE: R17.1 U16.7 | length 256.3
  Top Layer w24: R17.1 ccw(c10787.3,5637.4) U16.7@11019.86,5390.61
CM_OUT: R45.2 U8.52 | length 130
  Top Layer w8: R45.2@9088.3,5478.3 9135,5525 U8.52
DIAG_END: U14.21 U22.26 | length 556.1
  Top Layer w8: v1(10141.6,3940.4) 10152.9,3940.4 10156.7,3944.2 10175,3944.2 10183,3936.1 U14.21
  Bottom Layer w8: v1(10141.6,3940.4) 10152.9,3940.4 10175.3,3962.8 10509.2,3962.8 10592.2,3879.7
DVDD: C3.2 C7.2 C8.2 C9.2 U8.27 U8.44 | length 348.7
  Top Layer w10: v1(8970.8,5538.3) 8977.5,5538.3 U8.44 ; C3.2@8975.8,6017.8 8975.8,5983.3 v1(8980.8,5978.3) 8977.5,5975 U8.27
  Bottom Layer w10: C8.2 C7.2 8940.8,5508.3 v1(8970.8,5538.3) ; C9.2@8920.8,6017.8 8920.8,5993.3 8935.8,5978.3 v1(8980.8,5978.3)
FB1: R51.1 R54.2 U4.6 | length 109.5
  Top Layer w10: R54.2@9210.8,6065.8 9210.8,6063.3 9215.8,6058.3 9258.3,6058.3 9273.7,6073.7 U4.6
FB2: R55.1 R83.2 U11.6 | length 101.2
  Top Layer w8: R83.2@8616.5,5886.4 R55.1
  Top Layer w10: R55.1@8696.6,5901.6 U11.6
GND: 
IOVDD: C22.2 C23.2 C46.2 C47.2 C48.2 C49.2 R55.2 U8.30 U8.41 U11.8 | length 497.6
  Top Layer w8: C23.2 8857.2,5883.9
  Top Layer w16: U11.8 C22.2@8802.7,5937.8 ; 8772.7,5942.8 8781.5,5951.6
  Bottom Layer w18: C48.2 C47.2 8836.3,5653.3 v1(8960.8,5653.3) v1(8990.8,5653.3) ; C49.2 C46.2 8916.3,5868.3 v1(8970.8,5868.3) v1(8995.8,5868.3)
  other v1: 9017.8,5653.5 9022.2,5869.7
LA: R10.1 U16.10 | length 346.6
  Top Layer w24: R10.1 10897.2,5889.7 ; 10895.5,5889.85 ccw(c11131.7,9185) U16.10
LDO1: R23.1 R57.1 U11.3 U25.25 | length 213.5
  Top Layer w8: v1(8567.2,6139.7) R23.1 8608.9,6135.5 R57.1
  Top Layer w10: R57.1 8643.9,6038.9 8681.5,6038.9 8696.6,6023.8
LDO2: R25.1 R52.1 U4.3 U25.23 | length 260.7
  Top Layer w8: v1(9087.2,6329.7) 9124.7,6329.7 9129.7,6324.7 9123.3,6318.3 ; R52.1 R25.1@9178.3,6308.3
  Top Layer w10: R52.1 9178.3,6228.7 9192.2,6214.7 9262.2,6214.7 9273.7,6203.2 U4.3
LED_ALM: U14.22 U22.25 | length 405.7
  Top Layer w8: v1(10165.9,3922.2) 10167.4,3920.6 10194.2,3920.6 U14.22
  Bottom Layer w8: v1(10165.9,3922.2) 10194.4,3950.7 10396.2,3950.7 10487.2,3859.7
LL: R11.1 U16.11 | length 345.1
  Top Layer w24: R11.1@10787.24,5748.22 cw(c10844.1,5619.3) 10832.31,5759.71 ; 10833.69,5759.81 cw(c11131.7,2210.9) U16.11@11131.7,5772.3
PD_ALM: U14.23 U22.24 | length 348.9
  Top Layer w8: v1(10142.2,3894.9) 10144.1,3896.7 U14.23
  Bottom Layer w8: v1(10142.2,3894.9) 10169.6,3894.9 10187.8,3913.1 10187.8,3920.4 10202.2,3934.7 10392.2,3934.7 10407.2,3919.7
PG1: R56.2 U11.5 U25.24 | length 150.4
  Top Layer w10: v1(8575.1,5984.1) 8605,6013.9 R56.2 8676.9,5946 U11.5
PG2: R35.2 U4.5 U25.22 | length 132.3
  Top Layer w10: v1(9172.1,6168.3) 9187.1,6183.3 R35.2 9240.8,6145.8 9240.8,6136.8 9254,6123.6 U4.5
RA: R12.1 U16.9 | length 362.3
  Top Layer w24: R12.1@10787.23,6048.37 ccw(c10907.2,6143.8) 10907.2,5990.5 U16.9
RL: C58.1 D14.3 R36.2 R44.1 U8.54 | length 1423.2
  Top Layer w8: U8.54 9174.4,5542.6 9202.2,5514.7 9241.8,5514.7 R44.1 9281.3,5475.3 C58.1 ; C58.1@9281.3,5357.8 v1(9335.8,5303.3) ; v1(9500.8,5308.3) 10075.8,5308.3 10132.2,5364.7 10206.4,5364.7 D14.3 10259.1,5374.1 R36.2
  Top Layer w10: C58.1@9276.3,5362.8 C58.1@9276.3,5363.3
  Bottom Layer w10: v1(9335.8,5303.3) 9495.8,5303.3 v1(9500.8,5308.3)
RLD: R16.1 U16.14 | length 333.5
  Top Layer w24: R16.1 cw(c10787.3,-13657.5) U16.14@11120.74,5445.39
RLD_SI: R43.2 R44.2 R45.1 U8.53 | length 219.8
  Top Layer w8: R45.1@9153.3,5478.3 9153.3,5587.6 U8.53
  Top Layer w10: R43.2@9155.8,5425.8 9155.8,5475.8 9153.3,5478.3 R44.2@9208.3,5478.3
SPARE: U16.13
SPO2_AFE_PDN2: U14.20
SPO2_DET_N: D5.3 U5.5 U14.1 | length 776
  Top Layer w8: U14.1 10450.6,3759 10453.4,3761.8 10630.4,3761.8 10725.1,3667.1 10793.5,3667.1 D5.3 10848.1,3667.1 10894.8,3667.1 cw(c10894.8,3661.1) 10900.8,3661.1 ccw(c10906.8,3661.1) 10912.8,3661.1 cw(c10918.8,3661.1) 10924.8,3661.1 ccw(c10930.8,3661.1) 10936.8,3661.1 cw(c10942.8,3661.1) 10942.8,3667.1 11029.5,3667.1 11038.9,3676.5 11046.9,3676.5 11052.5,3670.8 11052.5,3662.8 U5.5
SPO2_DET_P: D6.3 U5.9 U14.2 | length 777.2
  Top Layer w8: U14.2 10450.6,3778.6 10453.4,3775.8 10636.2,3775.8 10730.9,3681 10790,3681 D6.3 10844.6,3681 11023.7,3681 11033.1,3690.5 11052.7,3690.5 11062.4,3680.7 11127.7,3680.7 U5.9
SPO2_RX_ANA_SUP: C37.2 C82.2 C85.2 D5.2 D6.2 U14.31 U14.33 U14.39 U15.1 | length 1834.6
  Top Layer w6: U14.33@10263.62,3733.32 cw(c9693,3683.4) C37.2@10265.8,3683.4
  Top Layer w8: U14.31 10227.2,3730.1 10227.2,3709.7 10259.7,3677.3 C37.2 v1(10292.2,3674.7) ; U15.1 10239.7,4097.3 C85.2 v1(10240.7,4129.7) ; U14.39 10381.8,3702.7 C82.2 10444.7,3719.7 10612.2,3719.7 v1(10647.2,3684.7) 10647.2,3624.7 10662.2,3609.7 10817.2,3609.7 10846.4,3580.6 D5.2 ; v1(10752.2,3774.7) 10788.3,3774.7 D6.2
  Bottom Layer w8: v1(10240.7,4129.7) 10102.2,3991.2 10102.2,3729.7 10152.2,3679.7 10287.2,3679.7 v1(10292.2,3674.7) v1(10384.1,3674.7) ; v1(10647.2,3684.7) 10647.2,3754.7 10667.2,3774.7 v1(10752.2,3774.7)
SPO2_VBG: C63.2 U14.7 | length 83.9
  Top Layer w8: U14.7 10509.5,3877.1 C63.2
SPO2_VCM_AFE: R47.2 U14.4 | length 83.5
  Top Layer w8: U14.4 10510.4,3818 R47.2
SPO2_VCM_SHIELD: C79.2 R47.1 | length 41.8
  Top Layer w8: R47.1 10590.7,3818.3 C79.2
V1: R13.1 U16.12 | length 361
  Top Layer w24: R13.1 cw(c10947.9,5437.7) 10942.35,5664.73 ; 10943.59,5664.83 cw(c11014.8,2750.9) U16.12@11131.78,5663.35
V2: R15.1 U16.1 | length 280.5
  Top Layer w24: R15.1 ccw(c11215.2,6627) 10927.35,6094.64 ; 10927.2,6094.7 U16.1
V3: U16.2
V4: U16.3
V5: U16.4
V6: U16.5
VBUS: C12.2 C59.2 C60.2 U22.11 U22.12 U23.13 | length 83.4
  Top Layer w8: U23.13 9037.7,3364.8 C60.2
VDD: R37.2
XOUT: C11.1 U8.45 U20.3 | length 189.1
  Top Layer w8: U20.3 8971.7,5416.2 C11.1 8997.2,5500.3 U8.45
pads on no net: U5.1 U5.4 U5.6 U5.8 U8.24 U8.25 U8.26 U8.37 U8.38 U8.39 U8.40 U8.46 U8.47 U14.5 U14.6 U14.10 U14.29 U14.30 U14.34 U14.35 U16.8 U16.15 U20.1 U21.2 U21.4 U21.5 U22.30 U22.31 U25.1 U25.2 U25.3 U25.4 U25.5 U25.6 U25.7 U25.8 U25.9 U25.10 U25.30 U25.31

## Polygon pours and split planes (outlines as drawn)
GND on Bottom Layer (solid, remove dead copper, pour order 6): 3000,7267.7 6537.2,7267.7 6537.2,5294.7 3000,5294.7
+VPS on Inner2 (solid, remove dead copper): 8452.2,5719.7 8440,5743.2 8440,5813.7 8610.2,5983.9 8706.5,5983.9 8732.2,6009.7 8732.2,6249.7 8772.1,6289.6 9178.3,6289.6 9193.4,6304.7 9352.2,6304.7 9362.2,6294.7 9362.2,6244.7 9357.2,6239.7 9313.3,6239.7 9298.3,6254.7 8842.2,6254.7 8782.2,6194.7 8782.2,6012.2 8722.2,5952.2 8670.7,5952.2 8617.2,5898.7 8567.2,5837.1 8567.2,5724.7 8562.2,5719.7

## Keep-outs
Board Outline Layer:
  lines w10: 8252.2,3005 11452.2,3005 11452.2,6664.5 8252.2,6664.5 8252.2,3005 ; 8257.2,3000 11457.2,3000 11457.2,6659.5 8257.2,6659.5 8257.2,3000

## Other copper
Top Layer:
  region net IOVDD: 8890.8,5863.3 8889.7,5864.4 8889.7,5873.3 8955.8,5873.3 8960.8,5878.3 9025.8,5878.3 9025.8,5858.2 8960.8,5858.3 8955.8,5863.3
  region net +VPS: 9330.8,6228.3 9320.8,6218.3 9320.8,6173.3 9315.8,6168.3 9310.8,6168.3 9305.8,6173.3 9305.8,6213.3 9295.8,6223.3 9295.8,6268.7 9330.8,6268.7
  region net AVDD: 9438.5,6140.4 9450.8,6128.1 9450.8,6098.3 9440.8,6088.3 9417.2,6088.3 9392.2,6063.3 9392.2,6039.7 9305.8,5953.3 9305.8,5928.3 9280.9,5904.4 9208.3,5904.4 9208.3,5950.6 9266.8,5949.3 9350.8,6033.3 9350.8,6088.3 9345.8,6093.3 9320.8,6093.3 9309.2,6104.9 9309.2,6126.4 9330.1,6126.4 9344.1,6140.4
  region net BAT: 8437.2,3349.7 8442.2,3354.7 8697.2,3354.7 8712.2,3339.7 8812.2,3339.7 8817.2,3344.7 8857.2,3344.7 8862.2,3339.7 8862.2,3309.7 8857.2,3304.7 8682.2,3304.7 8672.2,3314.7 8438.1,3314.7 8437.2,3315.6
  region net AGND: 8432.2,3269.7 8442.2,3279.7 8667.2,3279.7 8677.2,3269.7 8802.2,3269.7 8812.2,3279.7 8852.2,3279.7 8857.2,3274.7 8857.2,3245.9 8773.4,3245.9 8767.2,3239.7 8437.2,3239.7 8432.2,3244.7
  region net 3V3: 10258.7,3978.3 10252.2,3984.7 10177.2,3984.7 10167.8,3994.1 10167.8,4015.4 10177.2,4024.7 10297.2,4024.7 10302.2,4019.7 10302.2,3989.7 10289.5,3977 10289.5,3947.5 10286.7,3944.7 10258.7,3944.7
  region net 3V3: 10401.9,3946.8 10396.1,3950.9 10396,3972.7 10422.2,4004.7 10422.2,4049.7 10427.2,4054.7 10457.2,4054.7 10462.2,4049.7 10462.2,3994.7 10453.2,3985.7 10423.2,3985.7 10407.3,3969.8 10406.1,3949.4
  region net +VPS: 8728.9,6010.3 8728.9,6050.3 8713.9,6065.3 8713.9,6102.1 8747,6102.1 8748.9,6100.3 8748.9,6040.3 8743.9,6035.3 8743.9,6010.3 8738.9,6005.3 8733.9,6005.3
  region net IOVDD: 8769.5,5957.1 8781.7,5969.3 8847.7,5969.3 8867.2,5949.7 8867.2,5894.9 8888.8,5873.3 8944.7,5873.3 8949.7,5868.3 8940.5,5859.1 8892.9,5859.1 8892.2,5859.7 8854.9,5859.7 8841.4,5873.3 8841.4,5916.6 8830.8,5925 8782.2,5924.7 8769.5,5937.6
  region net IOVDD: 8892.2,5653.3 8895.2,5656.4 8897,5657.8 8945.2,5657.8 8952.2,5664.7 9027.2,5664.7 9032.2,5659.7 9032.2,5644.7 9027.2,5639.7 8957.2,5639.7 8952.2,5644.7 8895.4,5644.7 8892.1,5648
  region net +VPS: 8713.9,6053.7 8713.9,6126.4 8717.2,6129.7 8777.2,6129.7 8782.2,6124.7 8782.2,6084.7 8752.2,6054.7 8747.2,6054.7 8746.2,6053.7
  region net +VPS: 9295.8,6229.8 9295.8,6298.3 9302.2,6304.7 9352.2,6304.7 9362.2,6294.7 9362.2,6244.7 9357.2,6239.7 9342.3,6239.7 9330.8,6228.3 9297.4,6228.3
  region net +VPS: 8452.2,5719.7 8442.2,5729.7 8442.2,5764.7 8447.2,5769.7 8467.2,5789.7 8562.2,5789.7 8567.2,5784.7 8567.2,5764.7 8567.2,5759.7 8567.2,5724.7 8562.2,5719.7
Inner2:
  region net IOVDD: 9020.8,5638.3 8915.8,5638.3 8910.8,5643.3 8910.8,5658.3 8915.8,5663.3 8970.8,5663.3 8980.8,5673.3 8980.8,5848.3 8970.8,5858.3 8915.8,5858.3 8910.8,5863.3 8910.8,5868.3 8915.8,5873.3 8975.8,5873.3 8980.8,5878.3 9025.8,5878.3 9030.8,5873.3 9030.8,5648.3
  region net AVDD: 9100.8,5503.8 9090.8,5513.8 9102.2,5525.2 9102.2,5559.7 9091.2,5570.8 9090.8,5570.5 9090.8,5987.9 9096.2,5993.3 9130.8,5993.3 9135.8,5988.3 9135.8,5963.3 9150.8,5948.3 9265.8,5948.3 9280.8,5963.3 9295.8,5963.3 9305.8,5953.3 9305.8,5928.3 9275.8,5898.3 9255.8,5898.3 9170.8,5813.3 9170.8,5763.3 9213.8,5720.3 9213.8,5589 9224.5,5578.3 9275.8,5578.3 9290.8,5563.3 9290.8,5543.3 9274.2,5526.7 9153.3,5526.7 9153.3,5524 9133.1,5503.8

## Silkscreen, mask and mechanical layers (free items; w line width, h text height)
Top Silkscreen Layer:
  region: 71 vertices and 1 holes, not listed, extent 13281.1,4600.9 13440.8,4730.3
  region: 13352.6,4661.6 13349.1,4666.8 13345.9,4671.9 13347.1,4672.6 13349.9,4674.3 13352.7,4675.9 13353.9,4676.6 13352.9,4677.2 13350.4,4678.8 13347.7,4680.5 13346.5,4681.4 13345.7,4683 13345.8,4684.3 13346.5,4685 13350.3,4687.6 13353.7,4690.1 13353.5,4690.2 13352.4,4690.9 13350,4692.3 13346.5,4694.5 13345.5,4695.5 13345.2,4696.1 13345.3,4696.7 13345.7,4697.8 13346.7,4698.9 13347.4,4699.5 13358.8,4705.7 13366.8,4710 13370.2,4711.8 13373.2,4707 13376.1,4702.2 13374.9,4701.4 13371.9,4699.5 13367.7,4697 13367.9,4696.9 13369,4696.1 13371.7,4694.5 13376.9,4690.6 13375.4,4688.2 13371.5,4685.6 13368.2,4683.4 13369.3,4682.8 13371.8,4681.3 13376.5,4678.1 13376.4,4675.6 13376.1,4675.1 13375,4674.3 13371.5,4672.3 13364.2,4668.2 13356.1,4663.5
  lines w13.8: 12119.7,4711 12143.5,4734.8 ; 12146.1,4674 12146.1,4735.7 ; 12146.1,4736.6 12167.3,4715.4 ; 12329.7,4701 12353.5,4724.8 ; 12356.1,4664 12356.1,4725.7 ; 12356.1,4726.6 12377.3,4705.4 ; 12534.7,4703.6 12558.5,4727.4 ; 12561.1,4666.5 12561.1,4728.3 ; 12561.1,4729.1 12582.3,4707.9 ; 12655.9,4602.4 12655.9,4730.7 ; 12695.9,4600.9 12695.9,4730.5
  text "编号：JLC04161H-3313（成品板厚 1.56mm ±10%） / 成品板厚：1.6mm / 外层铜厚：1 oz / 内层铜厚：0.5 oz /  / +------+---------------------------+----------+-----------+ / | 层名 | 材料                      | 厚度(mil) | 厚度(mm)  | / +------+---------------------------+----------+-----------+ / | L1   | 外层铜厚 1oz              | 1.38     | 0.0350    | / |      | PP 3313 RC57% 4.2mil      | 3.91     | 0.0994    | / +------+---------------------------+----------+-----------+ / | L2   | 内层铜厚                  | 0.60     | 0.0152    | / +------+---------------------------+----------+-----------+ / |      | 芯板 1.3mm H/HOZ 含铜      | 49.80    | 1.2650    | / +------+---------------------------+----------+-----------+ / | L3   | 内层铜厚                  | 0.60     | 0.0152    | / +------+---------------------------+----------+-----------+ / |      | PP 3313 RC57% 4.2mil      | 3.91     | 0.0994    | / +------+---------------------------+----------+-----------+ / | L4   | 外层铜厚 1oz              | 1.38     | 0.0350    | / +------+---------------------------+----------+-----------+" at 10432.2,7124.7 h120
  text "DANGER: HIGH  / VOLTAGE (5kV)" at 13255.9,4735.7 h66.9 r180
  text "CAUTION: 700V" at 12595.9,4660.7 h66.9 r180

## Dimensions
11317.2,6414.7 to 9584.9,6414.7 on Document Layer
8417.2,6374.7 to 9638.3,6374.7 on Document Layer
9778.3,2709.7 to 10026.1,2709.7 on Document Layer
8432.2,2992.1 to 8432.2,3189 on Document Layer
7942.2,6663.6 to 7942.2,5687.2 on Document Layer
7987.2,3002.1 to 7987.2,4229.9 on Document Layer
8157.2,6663.6 to 8157.2,5858.6 on Document Layer
11337.2,2744.7 to 10156.1,2744.7 on Document Layer
10157.2,2425.1 to 11452.2,2425.1 on Document Layer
